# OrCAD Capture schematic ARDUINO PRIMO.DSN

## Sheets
1 00_Revision History: title: Revision History; rev: 3.0; company: dog hunter Inc.; note: Freedog; note: 8F-4, No.17, Ln. 91, Sec. 1,; note: Neihu Rd., Neihu Dist., Taipei City
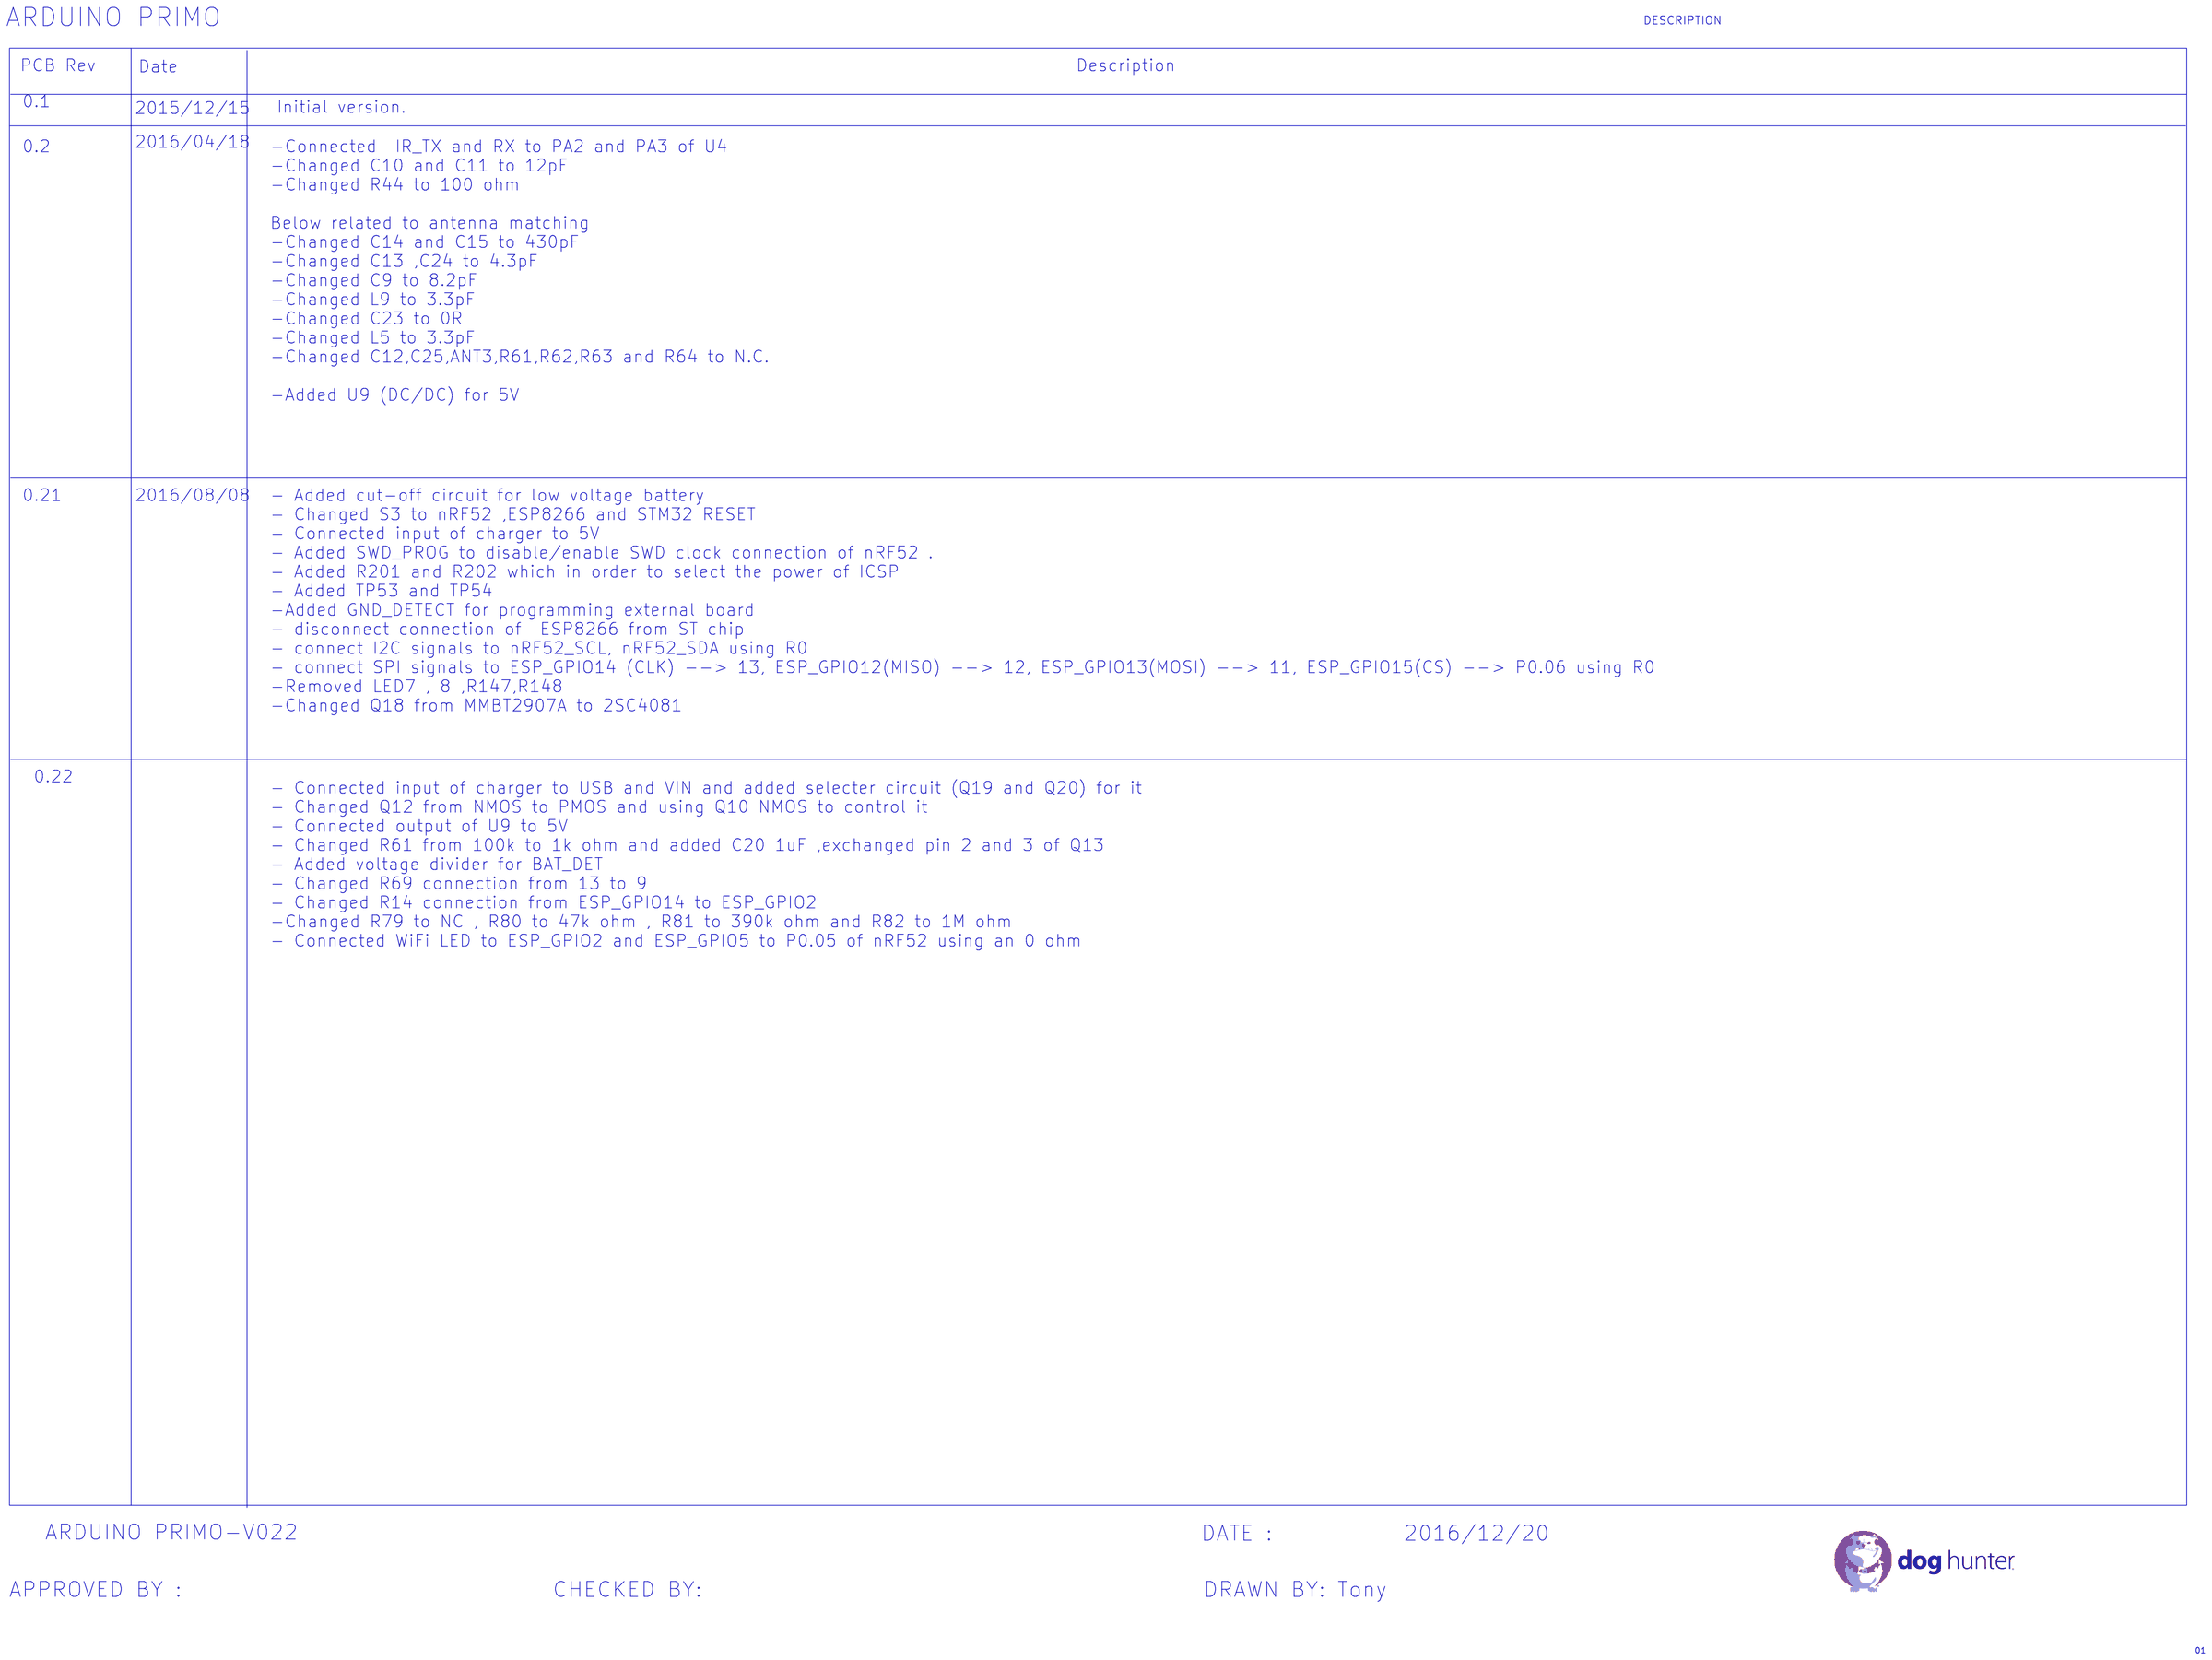
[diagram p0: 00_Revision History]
2 01_Block_Diagram: title: Block Diagram
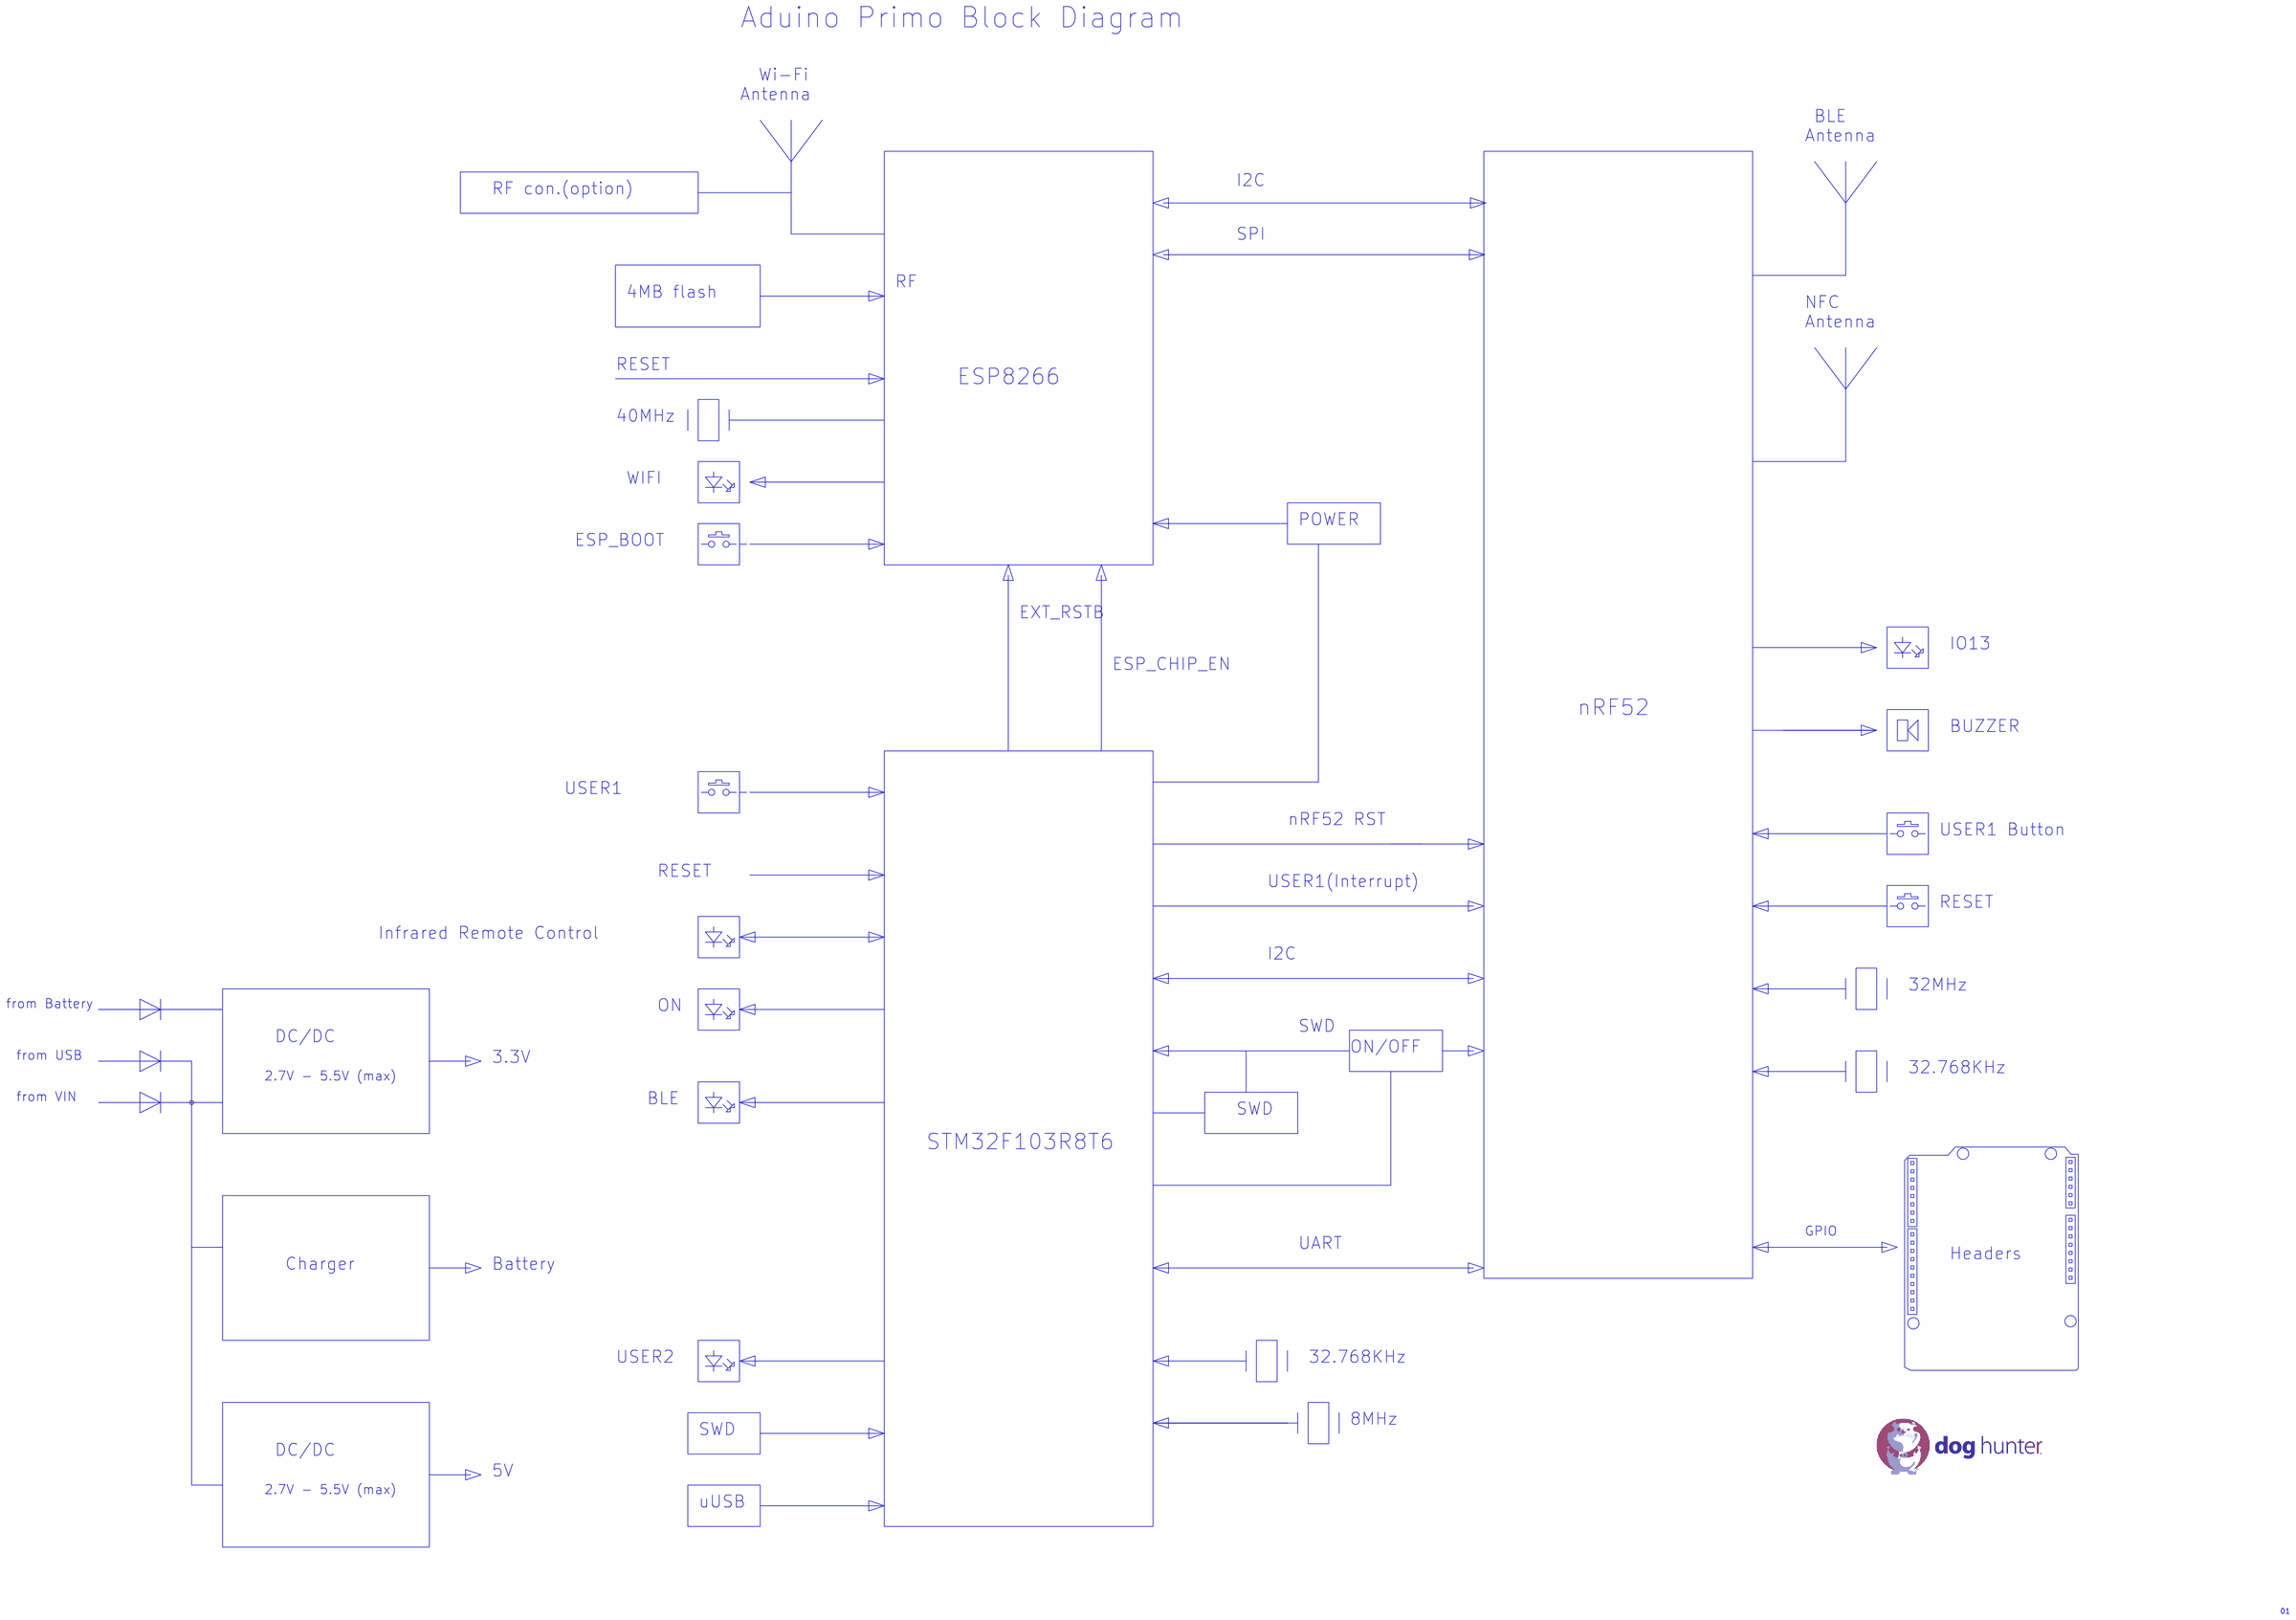
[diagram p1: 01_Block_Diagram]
3 02_Power_Block_Diagram: title: Power Block Diagram
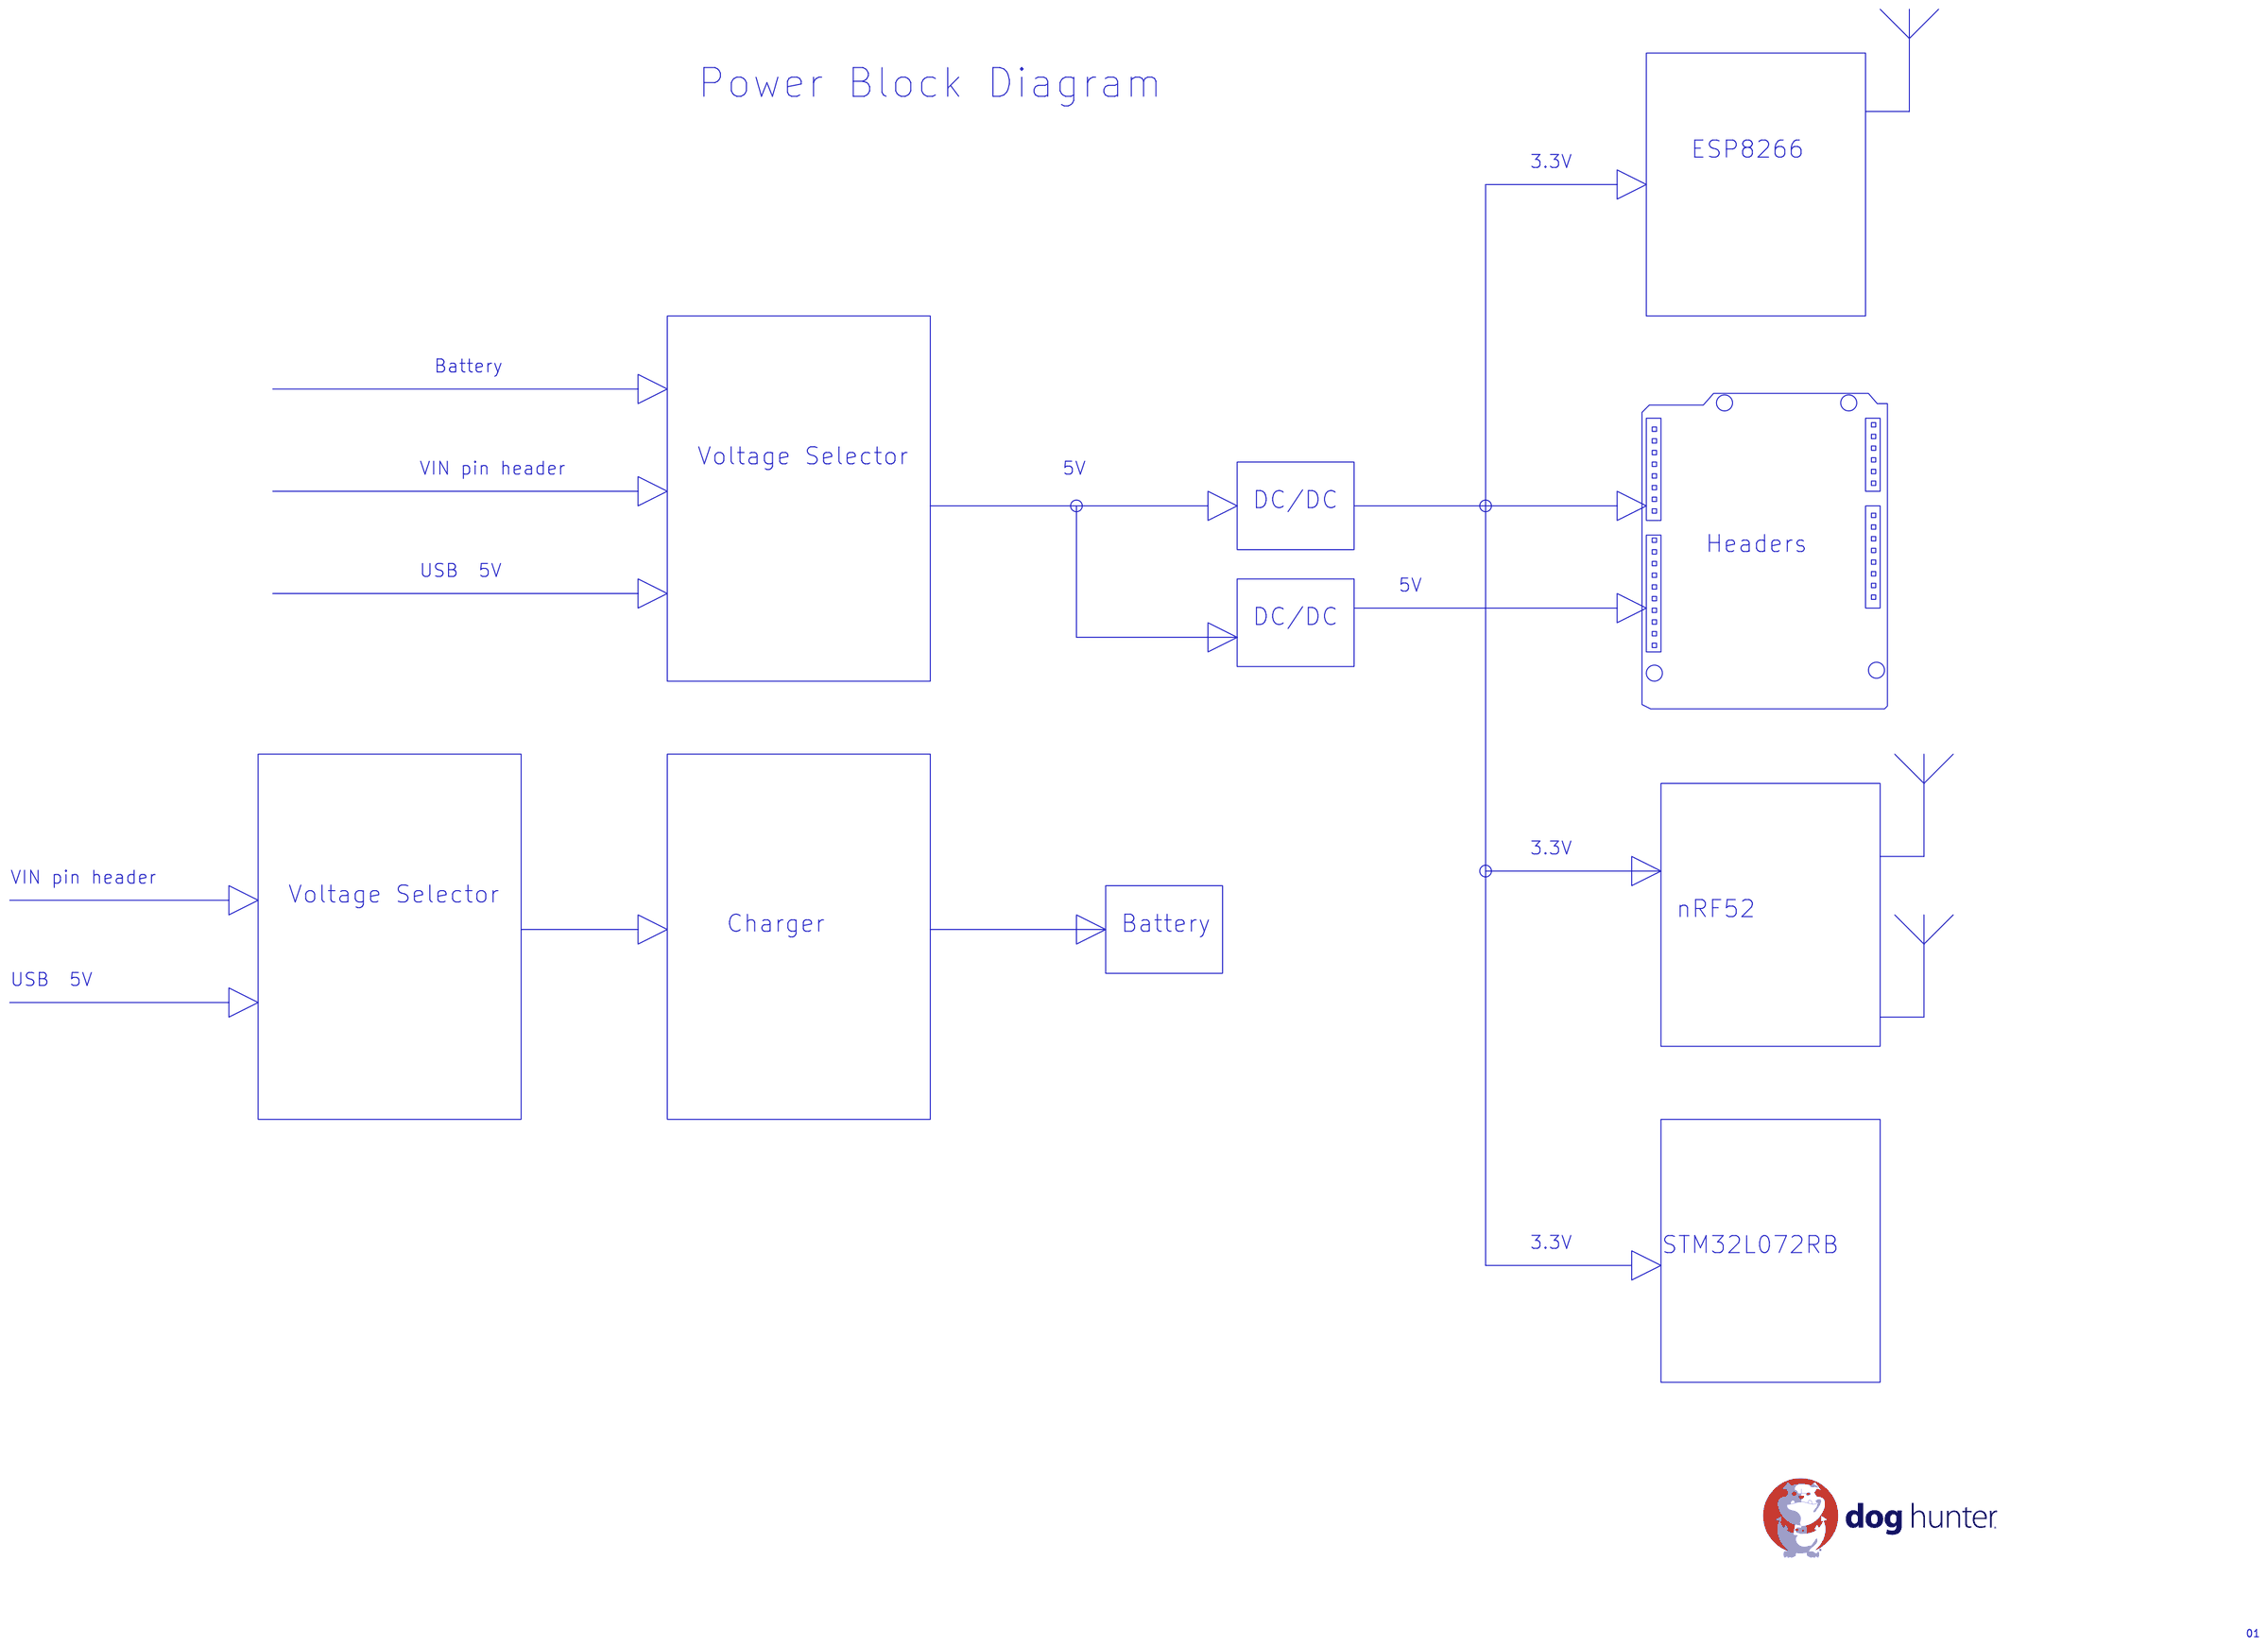
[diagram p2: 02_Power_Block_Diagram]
4 03_nRF52: size Custom; title: ATMEGA16U2 / ATMEGA328P
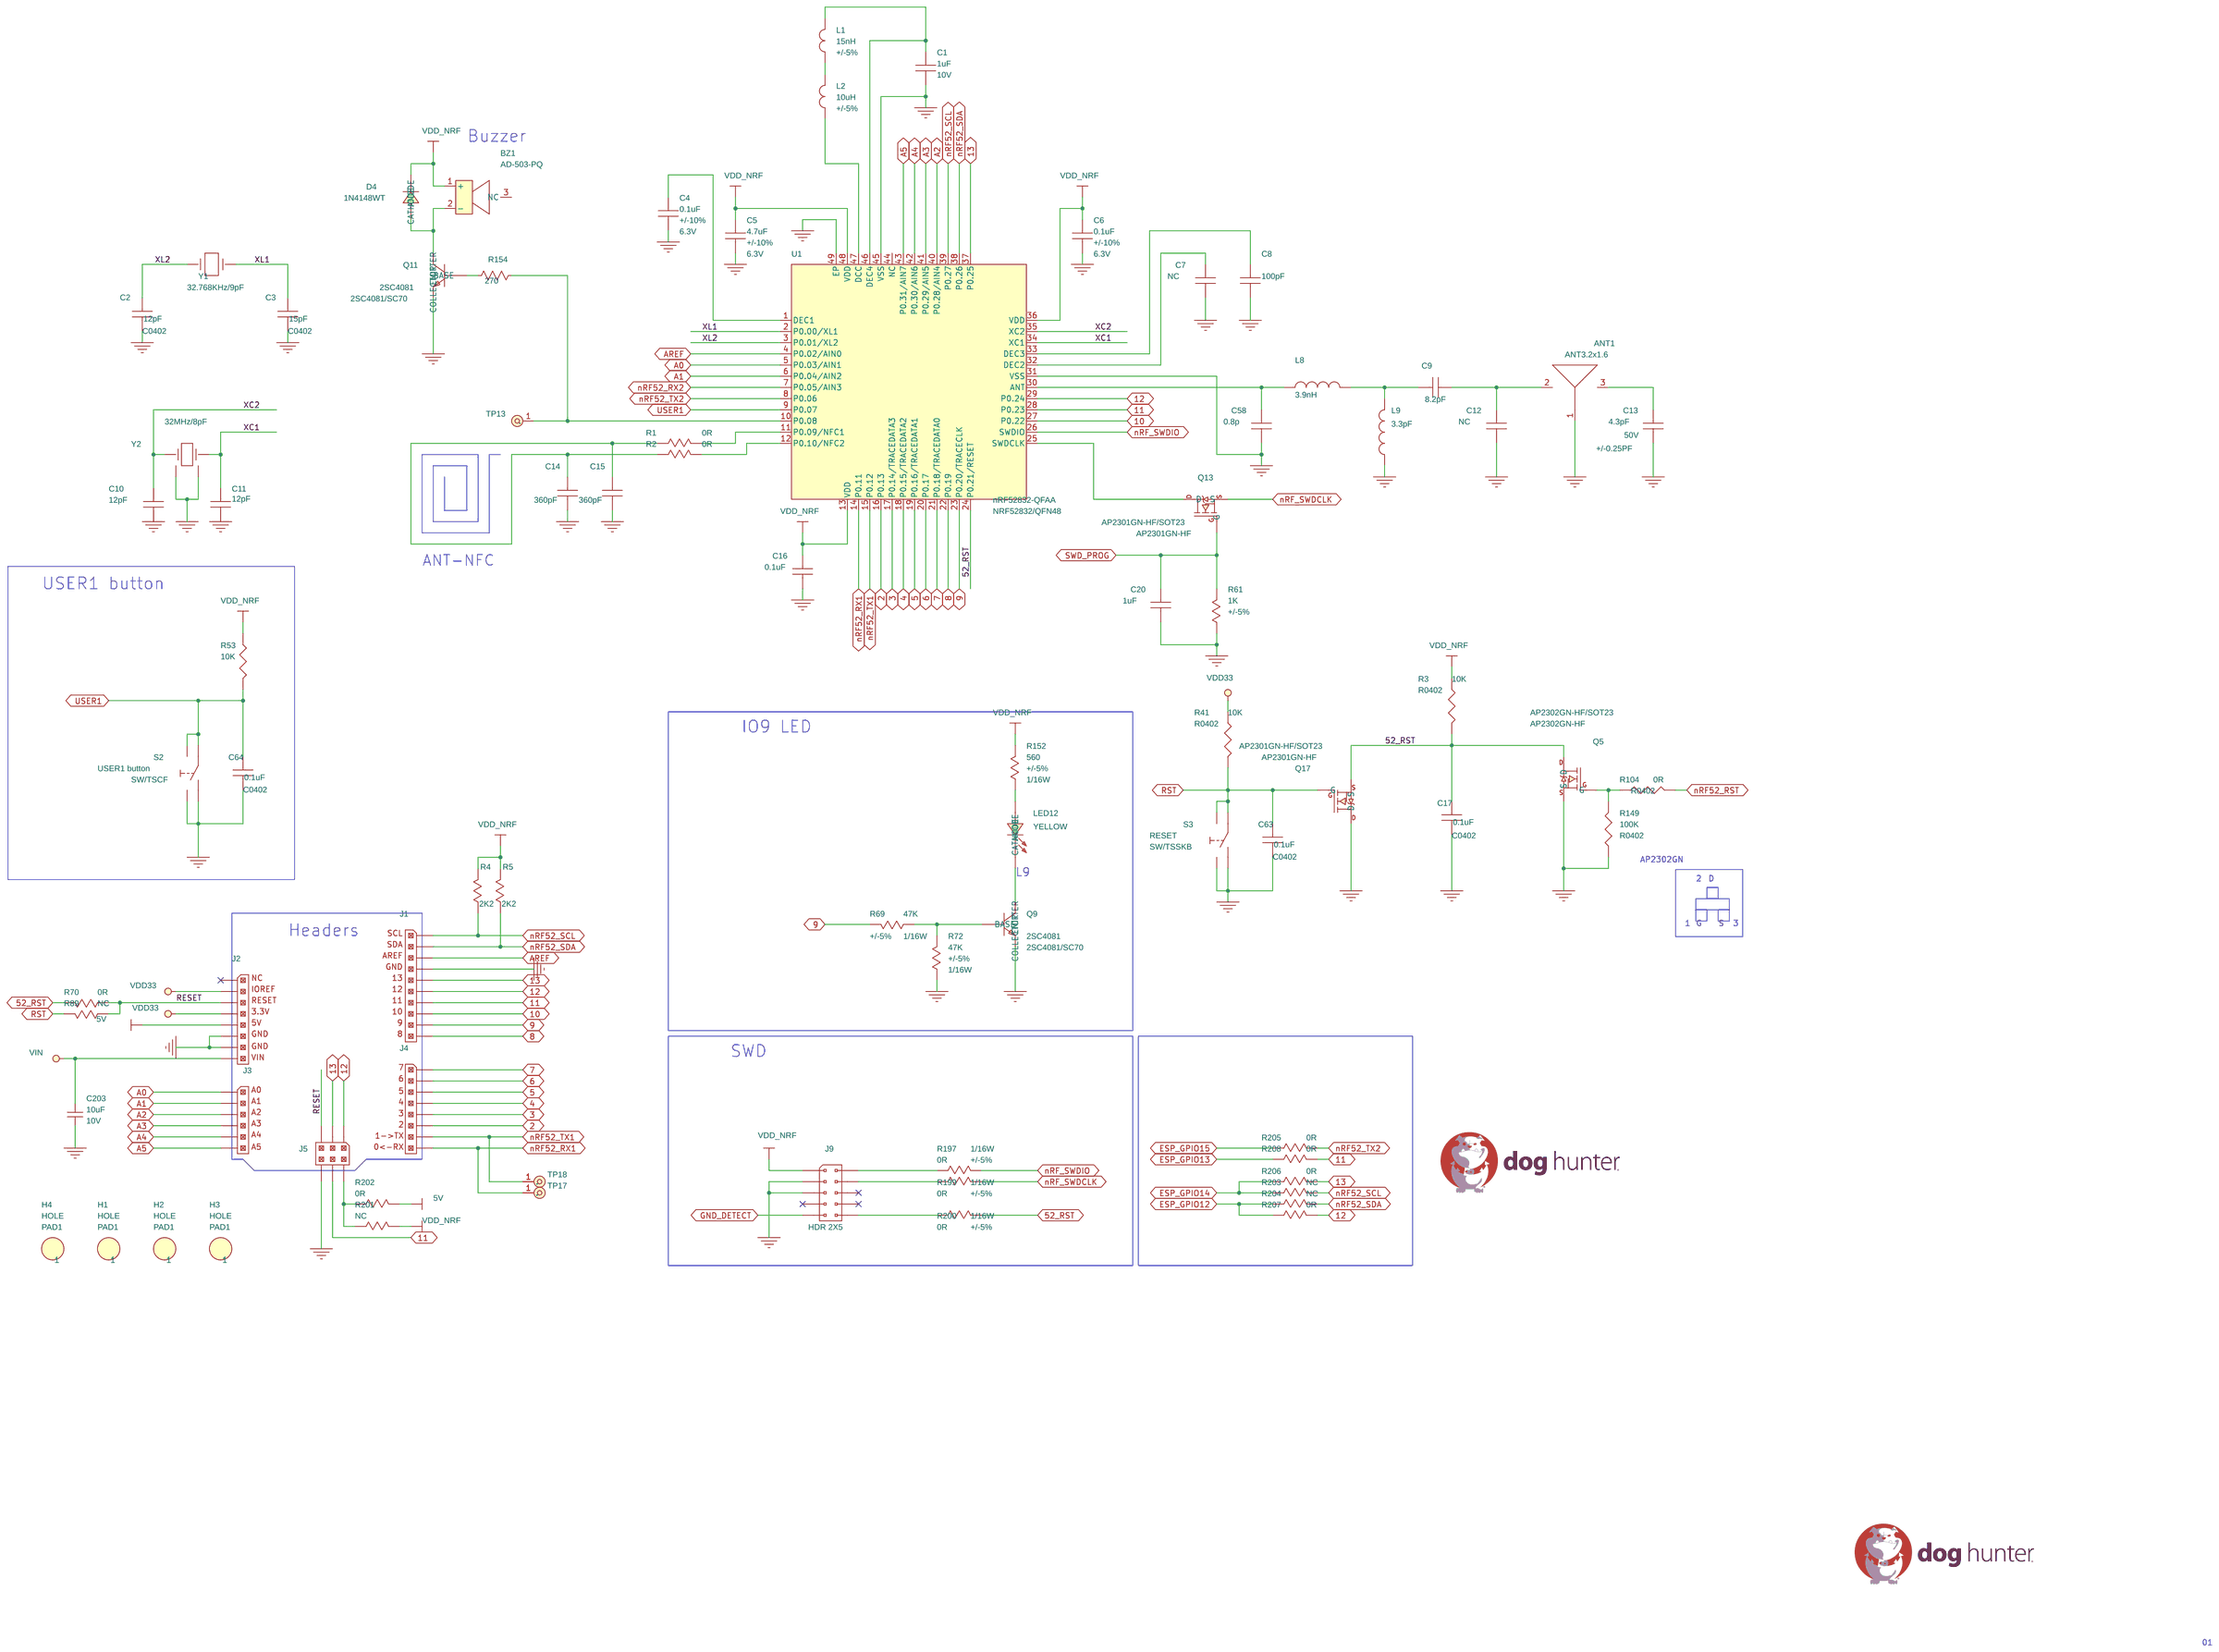
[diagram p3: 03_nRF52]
5 04_ESP8266: size A3; title: ESP8266
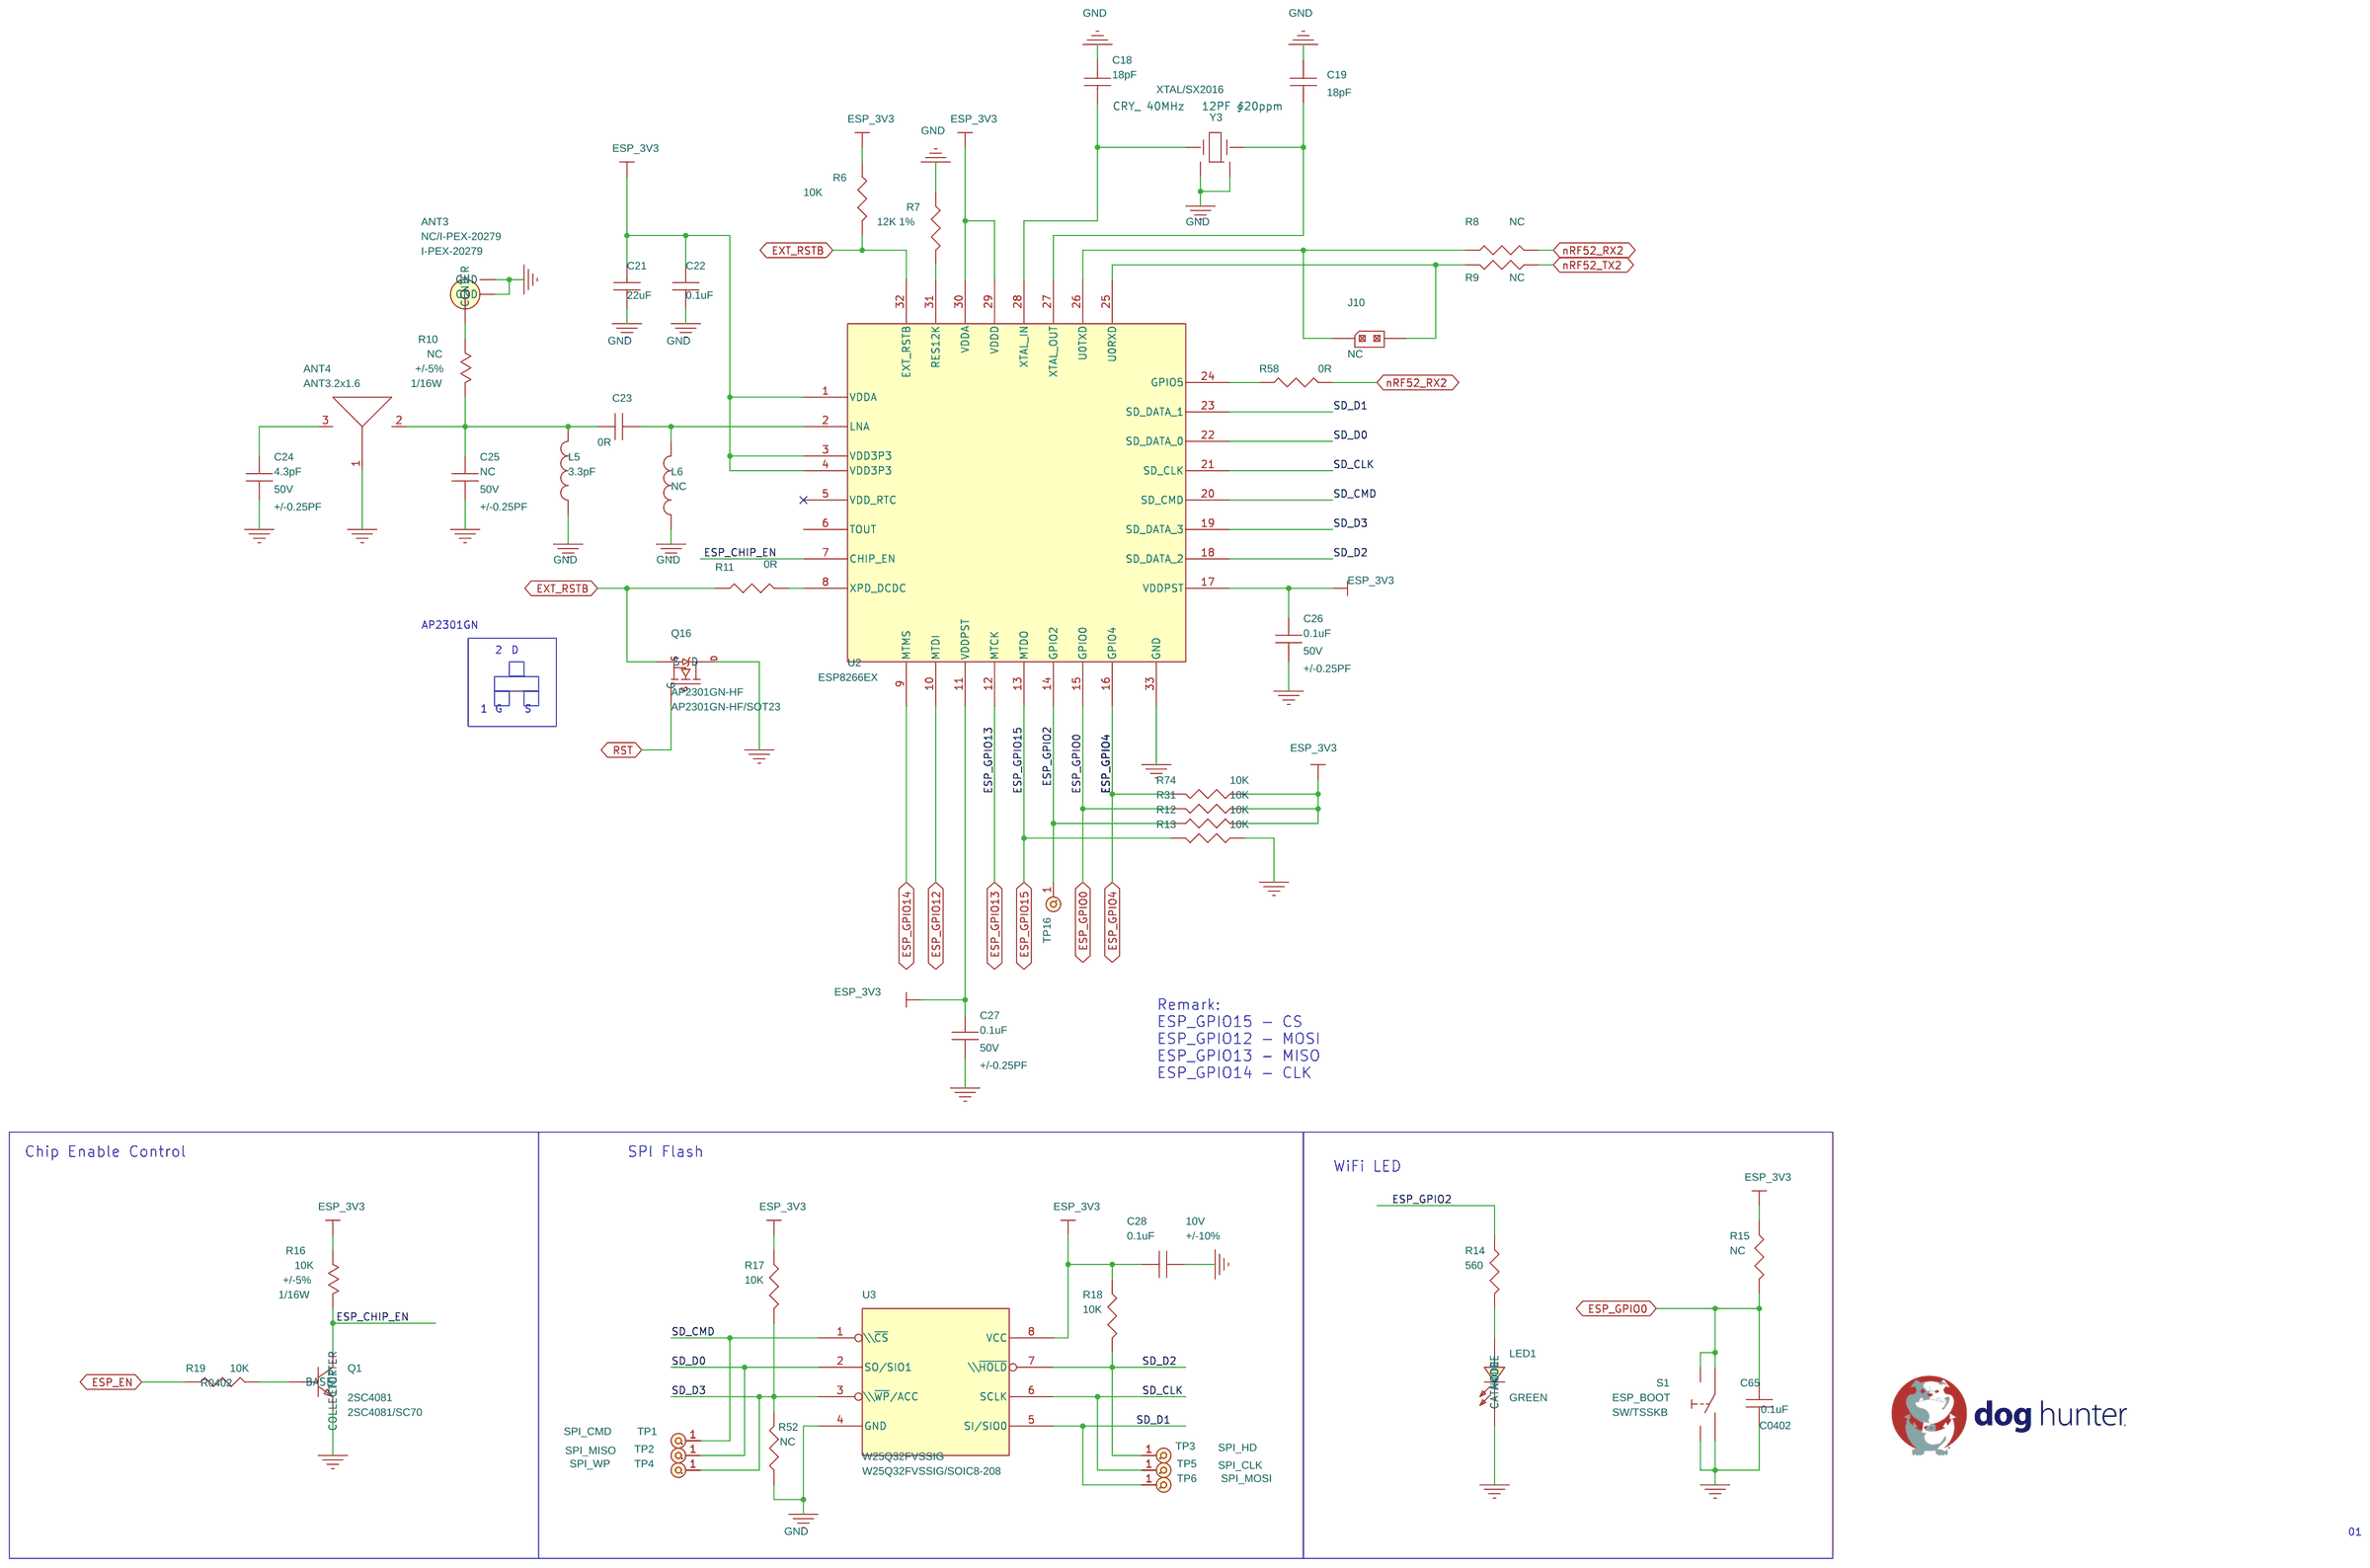
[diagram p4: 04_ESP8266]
6 05_ST: size A3; title: ST
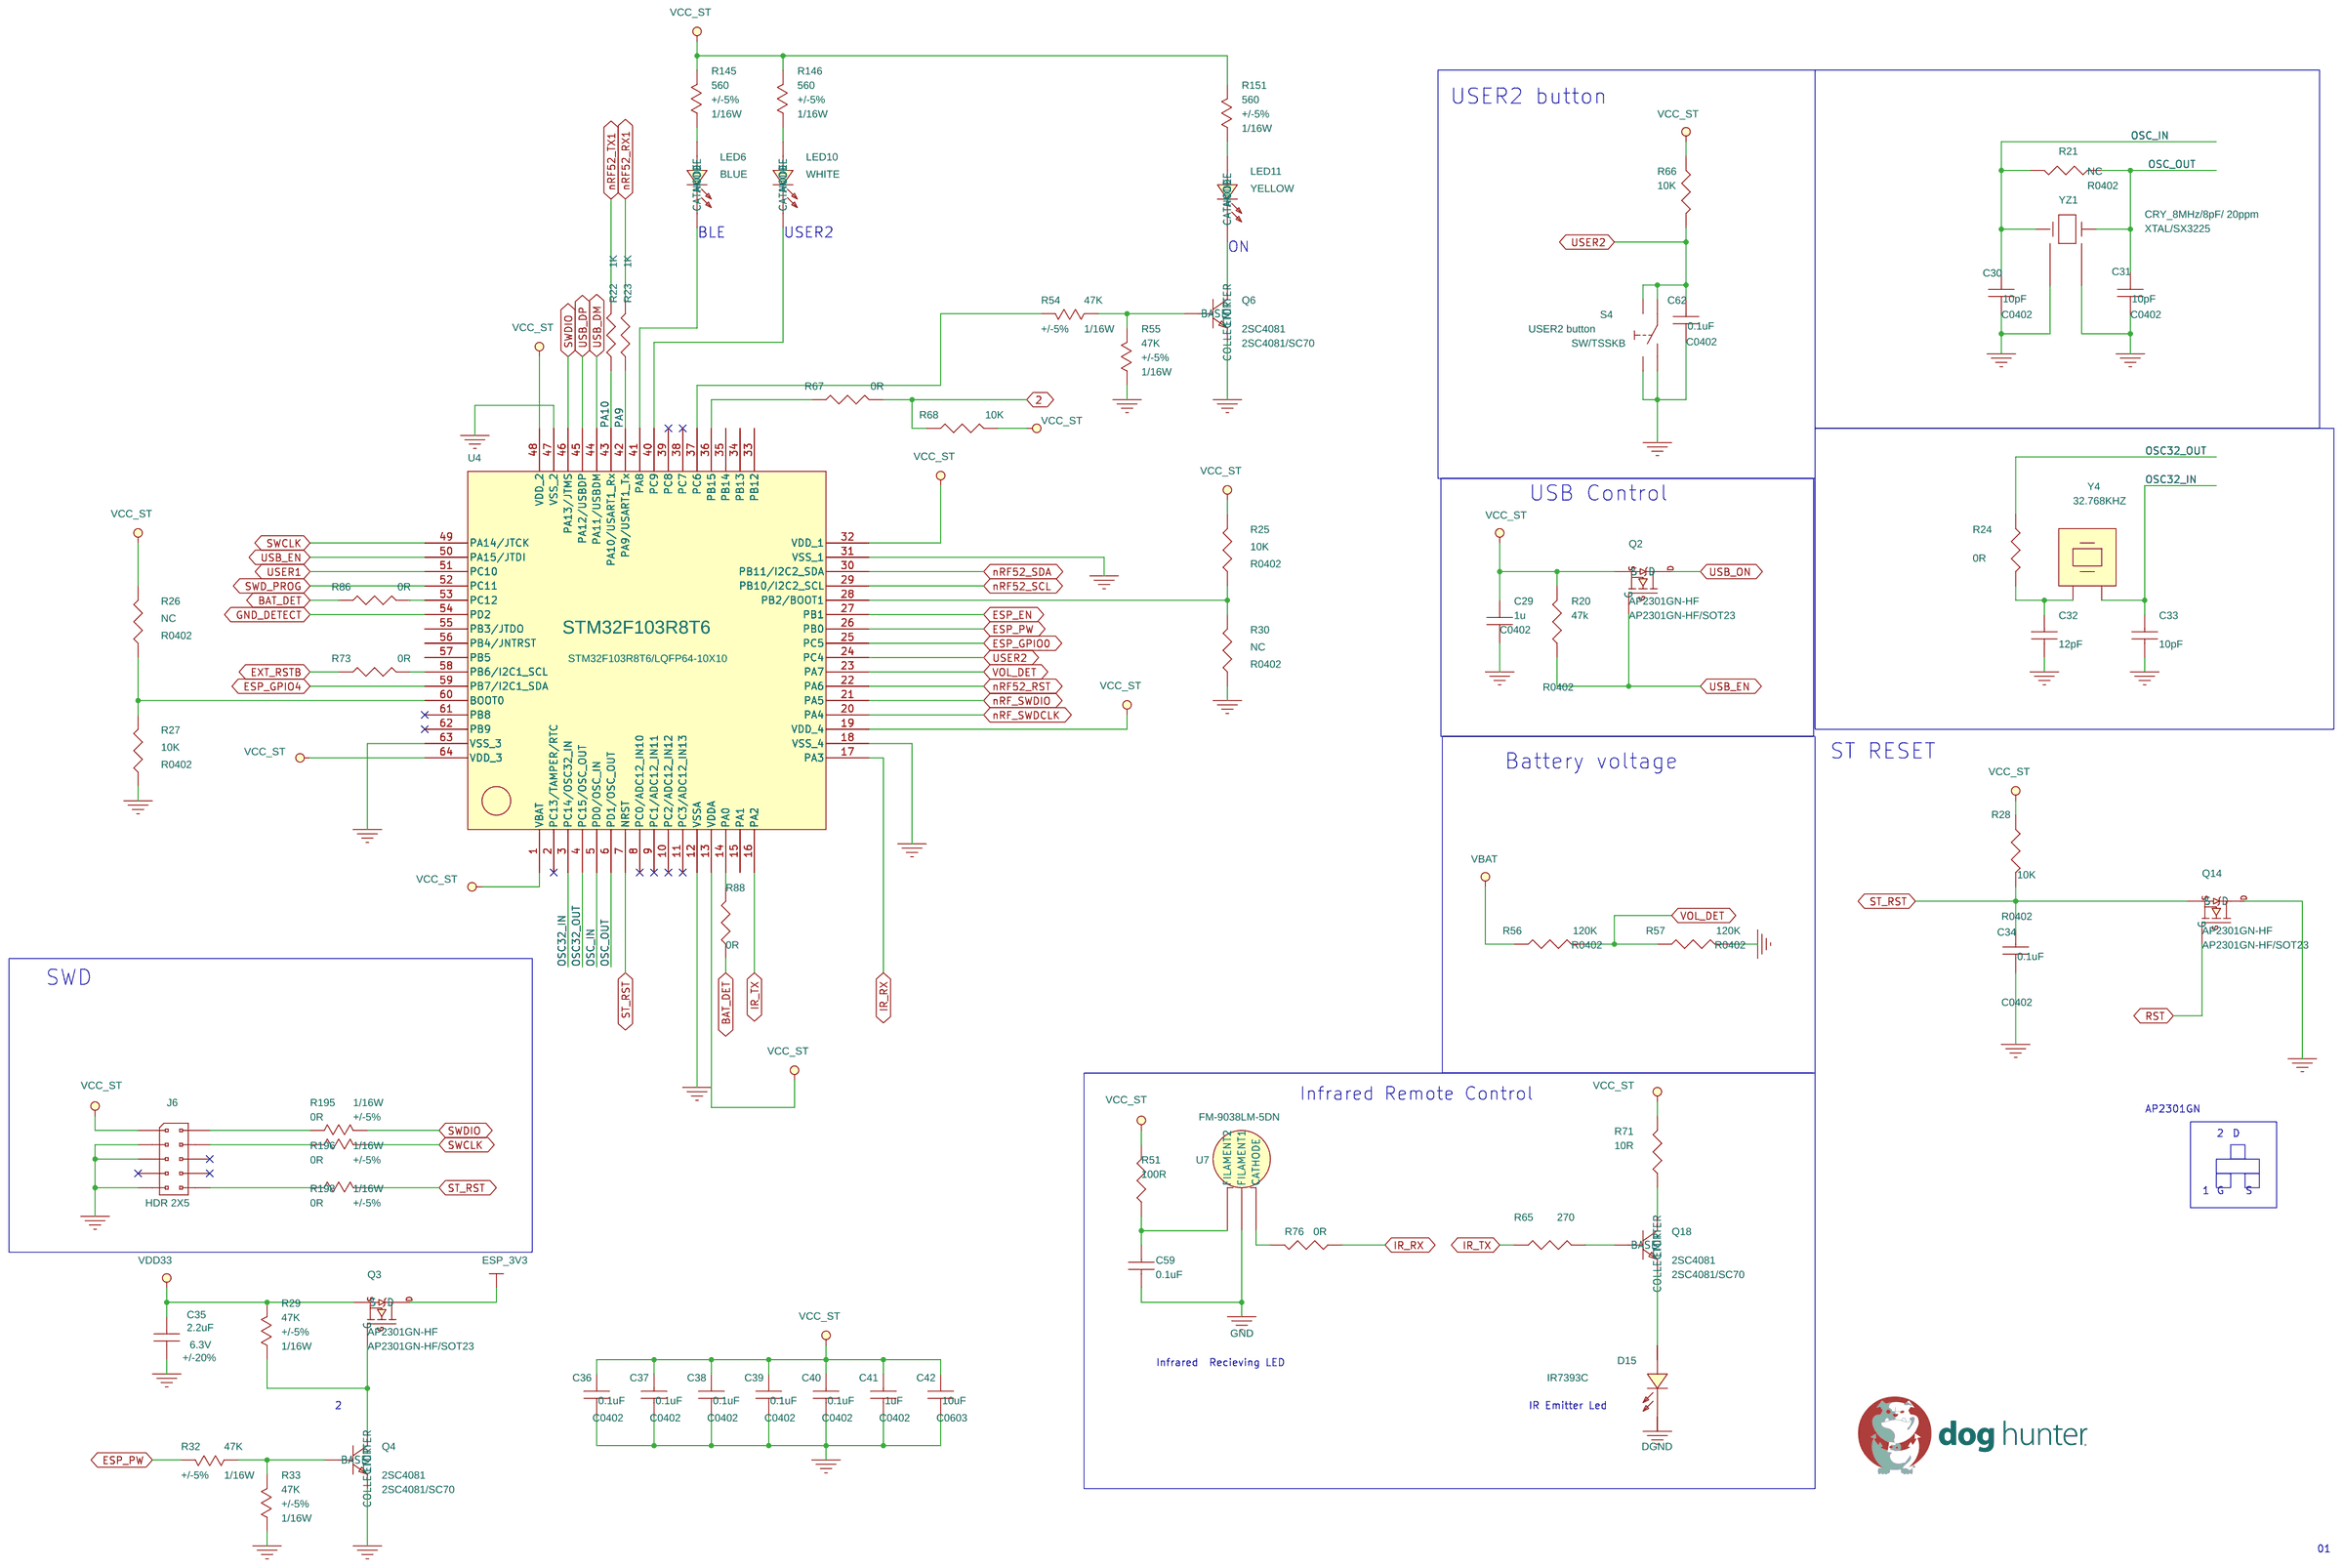
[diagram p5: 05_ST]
7 06_Power: size Custom; title: ST
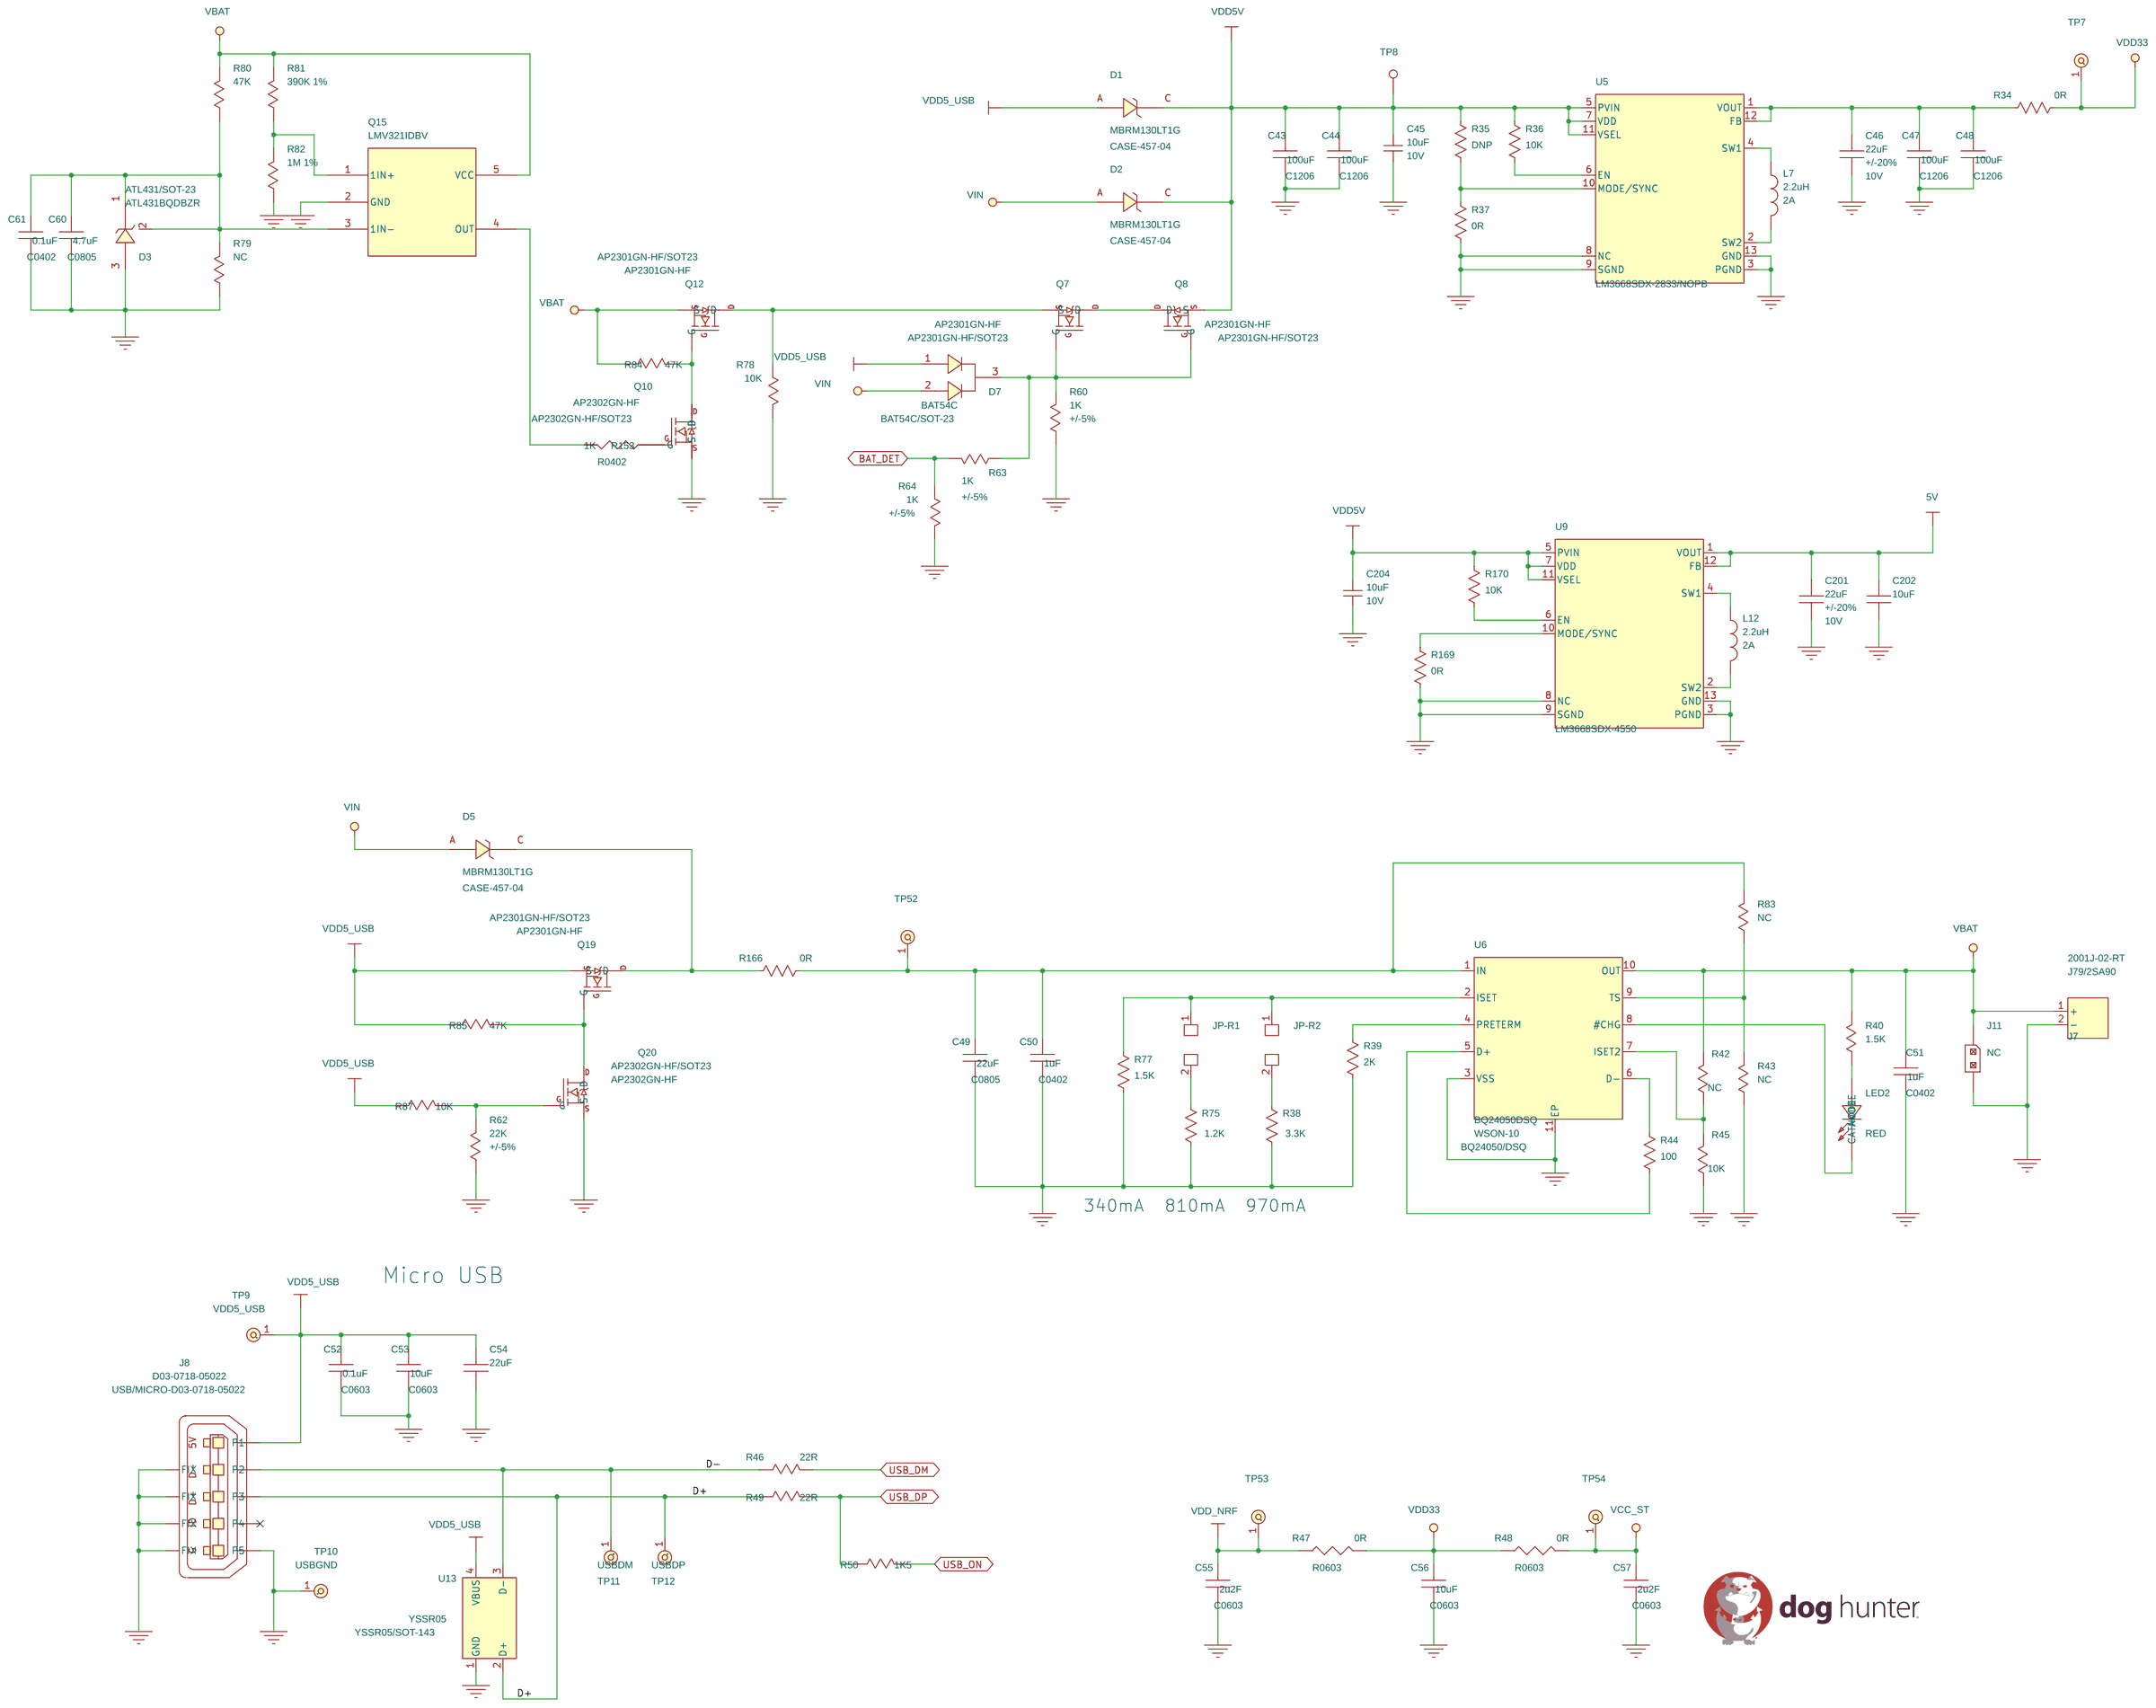
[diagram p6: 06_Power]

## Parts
sheet 03_nRF52
ANT1  ANT3.2x1.6  [ANT-3.2X1.6]
BZ1  AD-503-PQ  [AD-503-PQ]
C1  1uF  [C0402]
C2  12pF  [C0402]
C3  15pF  [C0402]
C4  0.1uF  [C0603]
C5  4.7uF  [C0603]
C6  0.1uF  [C0402]
C7  NC  [C0402]
C8  100pF  [C0402]
C9  8.2pF  [C0402]
C10  12pF  [C0402]
C11  12pF  [C0402]
C12  NC  [C0402]
C13  4.3pF  [C0402]
C14  360pF  [C0402]
C15  360pF  [C0402]
C16  0.1uF  [C0402]
C17  0.1uF  [C0402]
C20  1uF  [C0402]
C58  0.8p  [C0402]
C63  0.1uF  [C0402]
C64  0.1uF  [C0402]
C203  10uF  [C0805]
D4  1N4148WT  [SOD523]
H1  HOLE  [PAD1]
H2  HOLE  [PAD1]
H3  HOLE  [PAD1]
H4  HOLE  [PAD1]
J1  HEADER_2.54MM_VERT_PTH_10x1POS  [J100/10S]
J2  HEADER_2.54MM_VERT_PTH_8x1POS  [J100/8S]
J3  HEADER_2.54MM_VERT_PTH_6x1POS  [J100/6S]
J4  HEADER_2.54MM_VERT_PTH_8x1POS  [J100/8S]
J5  HEADER_2.54MM_VERT_PTH_3x2POS  [J100\6D]
J9  STRIP_1.27MM_VERT_PTH_5X2  [J50/10D]
L1  15nH  [L0402]
L2  10uH  [L0402]
L8  3.9nH  [L0402]
L9  3.3pF  [L0402]
LED12  YELLOW  [LED0603]
Q5  AP2302GN-HF  [AP2302GN-HF/SOT23]
Q9  2SC4081  [2SC4081/SC70]
Q11  2SC4081  [2SC4081/SC70]
Q13  AP2301GN-HF  [AP2301GN-HF/SOT23]
Q17  AP2301GN-HF  [AP2301GN-HF/SOT23]
R1  0R  [R0402]
R2  0R  [R0402]
R3  10K  [R0402]
R4  2K2  [R0402]
R5  2K2  [R0402]
R41  10K  [R0402]
R53  10K  [R0402]
R61  1K  [R0402]
R69  47K  [R0402]
R70  0R  [R0402]
R72  47K  [R0402]
R89  NC  [R0402]
R104  0R  [R0402]
R149  100K  [R0402]
R152  560  [R0402]
R154  270  [R0402]
R197  0R  [R0402]
R199  0R  [R0402]
R200  0R  [R0402]
R201  NC  [R0402]
R202  0R  [R0402]
R203  NC  [R0402]
R204  NC  [R0402]
R205  0R  [R0402]
R206  0R  [R0402]
R207  0R  [R0402]
R208  0R  [R0402]
S2  USER1 button  [SW/TSCF]
S3  RESET  [SW/TSSKB]
TP13  SPI_CMD  [PADA]
TP17  SPI_CMD  [PADA]
TP18  SPI_CMD  [PADA]
U1  nRF52832-QFAA  [NRF52832/QFN48]
Y1  32.768KHz/9pF  [XTAL/S2012R]
Y2  32MHz/8pF  [XTAL/SX2016]
sheet 04_ESP8266
ANT3  NC/I-PEX-20279  [I-PEX-20279]
ANT4  ANT3.2x1.6  [ANT-3.2X1.6]
C18  18pF  [C0402]
C19  18pF  [C0402]
C21  22uF  [C0603]
C22  0.1uF  [C0402]
C23  0R  [C0402]
C24  4.3pF  [C0402]
C25  NC  [C0402]
C26  0.1uF  [C0402]
C27  0.1uF  [C0402]
C28  0.1uF  [C0402]
C65  0.1uF  [C0402]
J10  NC  [J100/2S]
L5  3.3pF  [L0402]
L6  NC  [L0402]
LED1  GREEN  [LED0603]
Q1  2SC4081  [2SC4081/SC70]
Q16  AP2301GN-HF  [AP2301GN-HF/SOT23]
R6  10K  [R0402]
R7  12K 1%  [R0402]
R8  NC  [R0402]
R9  NC  [R0402]
R10  NC  [R0402]
R11  0R  [R0402]
R12  10K  [R0402]
R13  10K  [R0402]
R14  560  [R0402]
R15  NC  [R0402]
R16  10K  [R0402]
R17  10K  [R0402]
R18  10K  [R0402]
R19  10K  [R0402]
R31  10K  [R0402]
R52  NC  [R0402]
R58  0R  [R0402]
R74  10K  [R0402]
S1  ESP_BOOT  [SW/TSSKB]
TP1  SPI_CMD  [PADA]
TP2  SPI_MISO  [PADA]
TP3  SPI_HD  [PADA]
TP4  SPI_WP  [PADA]
TP5  SPI_CLK  [PADA]
TP6  SPI_MOSI  [PADA]
TP16  SPI_CMD  [PADA]
U2  ESP8266EX  [QFN32/ESP8266EX]
U3  W25Q32FVSSIG  [W25Q32FVSSIG/SOIC8-208]
Y3  CRY_ 40MHz   12PF ∮20ppm  [XTAL/SX2016]
sheet 05_ST
C29  1u  [C0402]
C30  10pF  [C0402]
C31  10pF  [C0402]
C32  12pF  [C0402]
C33  10pF  [C0402]
C34  0.1uF  [C0402]
C35  2.2uF  [C0402]
C36  0.1uF  [C0402]
C37  0.1uF  [C0402]
C38  0.1uF  [C0402]
C39  0.1uF  [C0402]
C40  0.1uF  [C0402]
C41  1uF  [C0402]
C42  10uF  [C0603]
C59  0.1uF  [C0603]
C62  0.1uF  [C0402]
D15  IR7393C  [IR7393C]
J6  STRIP_1.27MM_VERT_PTH_5X2  [J50/10D]
LED6  BLUE  [LED0603]
LED10  WHITE  [LED0603]
LED11  YELLOW  [LED0603]
Q2  AP2301GN-HF  [AP2301GN-HF/SOT23]
Q3  AP2301GN-HF  [AP2301GN-HF/SOT23]
Q4  2SC4081  [2SC4081/SC70]
Q6  2SC4081  [2SC4081/SC70]
Q14  AP2301GN-HF  [AP2301GN-HF/SOT23]
Q18  2SC4081  [2SC4081/SC70]
R20  47k  [R0402]
R21  NC  [R0402]
R22  1K  [R0402]
R23  1K  [R0402]
R24  0R  [R0402]
R25  10K  [R0402]
R26  NC  [R0402]
R27  10K  [R0402]
R28  10K  [R0402]
R29  47K  [R0402]
R30  NC  [R0402]
R32  47K  [R0402]
R33  47K  [R0402]
R51  100R  [R0402]
R54  47K  [R0402]
R55  47K  [R0402]
R56  120K  [R0402]
R57  120K  [R0402]
R65  270  [R0402]
R66  10K  [R0402]
R67  0R  [R0402]
R68  10K  [R0402]
R71  10R  [R0402]
R73  0R  [R0402]
R76  0R  [R0402]
R86  0R  [R0402]
R88  0R  [R0402]
R145  560  [R0402]
R146  560  [R0402]
R151  560  [R0402]
R195  0R  [R0402]
R196  0R  [R0402]
R198  0R  [R0402]
S4  USER2 button  [SW/TSSKB]
U4  STM32F103R8T6  [STM32F103R8T6/LQFP64-10X10]
U7  FM-9038LM-5DN  [IR/FM-9038LM-5DN]
Y4  32.768KHZ  [32768-CC7V-T1A]
YZ1  CRY_8MHz/8pF/ 20ppm  [XTAL/SX3225]
sheet 06_Power
C43  100uF  [C1206]
C44  100uF  [C1206]
C45  10uF  [C0805]
C46  22uF  [C0805]
C47  100uF  [C1206]
C48  100uF  [C1206]
C49  22uF  [C0805]
C50  1uF  [C0402]
C51  1uF  [C0402]
C52  0.1uF  [C0603]
C53  10uF  [C0603]
C54  22uF  [C0805]
C55  2u2F  [C0603]
C56  10uF  [C0603]
C57  2u2F  [C0603]
C60  4.7uF  [C0805]
C61  0.1uF  [C0402]
C201  22uF  [C0805]
C202  10uF  [C0603]
C204  10uF  [C0805]
D1  MBRM130LT1G  [CASE-457-04]
D2  MBRM130LT1G  [CASE-457-04]
D3  ATL431BQDBZR  [ATL431/SOT-23]
D5  MBRM130LT1G  [CASE-457-04]
D7  BAT54C  [BAT54C/SOT-23]
J7  2001J-02-RT  [J79/2SA90]
J8  MICRO_USB_5PIN_HORZ_SMD  [USB/MICRO-D03-0718-05022]
J11  NC  [J100/2S]
JP-R1  RESET-EN  [L0805-SHT]
JP-R2  RESET-EN  [L0805-SHT]
L7  2.2uH  [L/LPS4018]
L12  2.2uH  [L/LPS4018]
LED2  RED  [LED0603]
Q7  AP2301GN-HF  [AP2301GN-HF/SOT23]
Q8  AP2301GN-HF  [AP2301GN-HF/SOT23]
Q10  AP2302GN-HF  [AP2302GN-HF/SOT23]
Q12  AP2301GN-HF  [AP2301GN-HF/SOT23]
Q15  LMV321IDBV  [LMV321IDBV]
Q19  AP2301GN-HF  [AP2301GN-HF/SOT23]
Q20  AP2302GN-HF  [AP2302GN-HF/SOT23]
R34  0R  [R0402]
R35  DNP  [R0402]
R36  10K  [R0402]
R37  0R  [R0402]
R38  3.3K  [R0402]
R39  2K  [R0402]
R40  1.5K  [R0402]
R42  NC  [R0402]
R43  NC  [R0402]
R44  100  [R0402]
R45  10K  [R0402]
R46  22R  [R0402]
R47  0R  [R0603]
R48  0R  [R0603]
R49  22R  [R0402]
R50  1K5  [R0402]
R60  1K  [R0402]
R62  22K  [R0402]
R63  1K  [R0402]
R64  1K  [R0402]
R75  1.2K  [R0402]
R77  1.5K  [R0402]
R78  10K  [R0402]
R79  NC  [R0402]
R80  47K  [R0402]
R81  390K 1%  [R0402]
R82  1M 1%  [R0402]
R83  NC  [R0402]
R84  47K  [R0402]
R85  47K  [R0402]
R87  10K  [R0402]
R153  1K  [R0402]
R166  0R  [R0603]
R169  0R  [R0402]
R170  10K  [R0402]
TP7  VDD5V  [PADA]
TP8  TEST PAD  [PADA]
TP9  VDD5_USB  [PADA]
TP10  USBGND  [PADA]
TP11  USBDM  [PADA]
TP12  USBDP  [PADA]
TP52  VDD5V  [PADA]
TP53  VDD5V  [PADA]
TP54  VDD5V  [PADA]
U5  LM3668SDX-2833/NOPB  [LM3668-2833/WSON12]
U6  BQ24050DSQ  [BQ24050/DSQ]
U9  LM3668SDX-4550  [LM3668-2833/WSON12]
U13  YSSR05  [YSSR05/SOT-143]

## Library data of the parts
ANT1 ANT4 = ANT3.2x1.6
BZ1 = BUZZER_4P_0: BUZZER MAGN 3.6V 2.67KHZ SMT; Part Number: SMT-0927-S-6-R; Part Type: Buzzer
C1 = CAP: ATHEROS KEY: 031-104CK-022; AtherosDescription: CAP,0402,X7R,0.1uF,+/-10%,10V; CISPartType: Capacitor\0402; Tolerance: +/-10%; URL: 0; VendorDescription: equivalent of PHYCOMP / 04022F104M7B20D; VendorName: Yageo; VendorPart1: 662; Voltage: 10V
C2 C3 C30 C31 C43 C44 C47 C48 C52 C53 C62-C65 = 27PF_N_0402_5%
C4-C6 = CAP: ATHEROS KEY: 032-106CM-002; AtherosDescription: CAP,0603,X5R,10uF,+/-20%,10V; CISPartType: Capacitor\0603; Tolerance: +/-10%; Voltage: 6.3V
C7 C8 C12-C16 C20 C24-C27 C58 = CAP: ATHEROS KEY: 031-010CC-000; AtherosDescription: CAP,0402,NPO,1pF,+/-0.25pF,50V; CISPartType: Capacitor\0402; Tolerance: +/-0.25PF; Voltage: 50V
C9 C17-C19 C21-C23 C34 = CAP_NP
C10 C11 = CAP: ATHEROS KEY: 031-8R2CC-000; AtherosDescription: CAP,0402,NPO,8.2pF,+/-0.25pF,50V; CISPartType: Capacitor\0402; Tolerance: +/-0.25PF; Voltage: 50V
C45 C203 C204 = CAP_NP_v3: CAP CER 10UF 10V 10% X5R 0805; Package: 0805; Part Number: CAP_CER_10UF_10V_10%_X5R_ 0805; Part Type: Ceramic; Temp Coeff: X5R; Tolerance: 10%; Voltage: 10V
D4 = DIODE_TW: DIODE SWITCHING 75V 0.2A SOD523F; Current: 0.3A; Forward Voltage Drop: 1V a 50mA; Package: SOD-523F-2; Part Type: Rectifier; Voltage: 75V
H1-H4 = PAD
J1 = RECEPT_10X1_1: CONN RCPT 10POS .100" PTH; Part Type: Header
J2 = RECEPT_8X1_3: CONN RCPT 8POS .100" PTH; Part Type: Header
J3 = RECEPT_6X1_0: CONN RCPT 6POS .100" PTH; Part Type: Header
J4 = RECEPT_8X1_5: CONN RCPT 8POS .100" PTH; Part Type: Header
J5 = RECEPT_3X2: CONN RCPT 6POS DUAL .100" PTH; Part Type: Header
J6 J9 = STRIP_5X2: CONN HEADER 10POS DUAL .050" PTH; DESCR: HDR 2X5; Part Number: HEADER_1.27MM_VERT_PTH_5X2; Part Type: Berg Unshrouded
L1 = IND: ATHEROS KEY: 071-120LJ-000; AtherosDescription: IND,0402,12nH,+/-5%; CISPartType: Inductor\0402; Tolerance: +/-5%
L2 = IND_1: ATHEROS KEY: 071-120LJ-000; AtherosDescription: IND,0402,12nH,+/-5%; CISPartType: Inductor\0402; Tolerance: +/-5%
L5 L6 L8 L9 = INDUCTOR
LED6 LED10-LED12 = LED-0603-LTST-C190GKT_0: AtherosDescription: DIO,LED,GREEN CLEAR,0603,SMD; CISPartType: Diodes\LED
Q2 Q3 Q5 Q7 Q8 Q10 Q12-Q14 Q16 Q17 Q19 Q20 = MOSFET_N_0
Q1 Q4 Q6 Q9 Q18 = NPN_0: BJT NPN;50V;0.15A;SOT-323; Manufacturer: ROHM; yuhwei-footprint: SOT-323
Q11 = NPN_1: BJT NPN;50V;0.15A;SOT-323; Manufacturer: ROHM; yuhwei-footprint: SOT-323
R1 R2 R4 R5 = RES: ATHEROS KEY: 051-104RF-000; AtherosDescription: RES,0402,100K OHMS,+/-1%,1/16W; CISPartType: Resistor\0402; Tolerance: +/-1%; WATTAGE: 1/16W
R3 R47 R67 = R_1
R41 R73 = R_3
R6-R9 R11-R15 R31 R53 R58 R66 R74 R76 = RESISTOR_0
R10 R16 R29 R32 R33 R40 R42 R43 R45 R54 R55 R60-R64 R69 R70 R72 R78-R85 R87 R89 R145 R146 R151 R152 = RES: ATHEROS KEY: 051-103RJ-000; AtherosDescription: RES,0402,10K OHMS,+/-5%,1/16W; CISPartType: Resistor\0402; Tolerance: +/-5%; WATTAGE: 1/16W
R25 R104 R153 = R_2
R19 R23 R48 R149 = R
R154 = R_v3: RES 2.2K OHM 1/16W 5% 0402 SMD; Package: 0402; Part Number: RES_2.2K_OHM_1/16W_5%_0402_SMD; Part type: Thick film; Power: 1/16W; Tolerance: 5%
R195-R208 = RES: ATHEROS KEY: 051-102RJ-000; AtherosDescription: RES,0402,1K OHMS,+/-5%,1/16W; CISPartType: Resistor\0402; Tolerance: +/-5%; WATTAGE: 1/16W
S2 = SW_PUSHBUTTON_0
S1 S3 S4 = SW_PUSHBUTTON_2
TP1-TP7 TP9-TP13 TP16-TP18 TP52-TP54 = TP
U1 = nRF52832_0
Y1 = CRY_SM_24MHz_4P_0
Y2 = XTAL-TH-HC49-25MHz_3: AtherosDescription: XTAL,HC-49/S,Thru_Hole,25.000MHZ; CISPartType: Crystals
ANT3 = BNC_1
C28 = CAP: ATHEROS KEY: 031-104CK-022; AtherosDescription: CAP,0402,X7R,0.1uF,+/-10%,10V; CISPartType: Capacitor\0402; Tolerance: +/-10%; Voltage: 10V
J10 J11 = RECEPT_3X2_0: CONN RCPT 6POS DUAL .100" PTH; Part Number: HEADER_2.54MM_VERT_PTH_3x2POS; Part Type: Header
LED1 LED2 = LED-0603-LTST-C190GKT_0: AtherosDescription: DIO,LED,Yellow CLEAR,0603,SMD; CISPartType: Diodes\LED
R17 R18 R52 = R_0: P/N: 21-253-625101
U2 = ESP8080_5
U3 = MX25L3205D-8SOP: AtherosDescription: IC,Memory,MX25L6405DZNI-12G,64M-bit SPI FLASH, SO8; CISPartType: IC\Memory
Y3 = CRY_SM_24MHz_4P_1
C29 C32 C33 = CAP_NP_0
C35 = CAP: ATHEROS KEY: 030-104CK-001; AtherosDescription: CAP,0201,X5R,0.1UF,+/-10%,6.3V; CISPartType: Capacitor\0201; StandardCost-100K: 0; Tolerance: +/-20%; URL: 0; VendorDescription: CAP, MLCC, X5R, 0.1uF +/-10%, 10V, 0402, 7"T+R; VendorName: Yageo; VendorPartNumber: CC0402KRX5R6BB104; Voltage: 6.3V
C36-C42 C49-C51 C55-C57 C60 C61 = 0.1UF_0402_10V_10%
C59 = CAP
D15 = LED_1
R20 = R_8
R21 = RESISTOR_1: Type: 5%
R22 = R_10
R24 = R_0
R26 = RESISTOR_5: Type: 5%
R27 = RESISTOR_3: Type: 5%
R28 = R_9
R30 = RESISTOR_2: Type: 5%
R51 = RESISTOR_4
R56 = R_4
R57 = R_5
R65 = RESISTOR_6
R68 = R_6
R71 = RESISTOR
R86 = R_7
R88 = R_11
U4 = SM339Bx-80LQFP_14
U7 = TRIODE_1
Y4 = CRYSTAL_2
YZ1 = CRY_SM_24MHz_4P_6
C46 C201 = CAP: ATHEROS KEY: 033-226CM-001; AtherosDescription: CAP,0805,X5R,22uF,+/-20%,6.3V; CISPartType: Capacitor\0805; Tolerance: +/-20%; Voltage: 10V
C54 = CAP: ATHEROS KEY: 033-226CM-001; AtherosDescription: CAP,0805,X5R,22uF,+/-20%,6.3V; CISPartType: Capacitor\0805; Tolerance: +/-20%; Voltage: 6.3V
C202 = CAP: ATHEROS KEY: 032-106CM-001; AtherosDescription: CAP,0603,X5R,10uF,+/-20%,6.3V; CISPartType: Capacitor\0603; StandardCost-100K: 0; Tolerance: +/-20%; URL: 0; VendorDescription: CAP, MLCC, X5R, 1uF +/-10%, 10V, 0603, 7"T+R; VendorName: Yageo; VendorPart1: 309; VendorPartNumber: CC0603KRX5R6BB105; Voltage: 10V
D1 D2 D5 = BZX84C22_SOT_4: Foxlink_Description: DIODE,SCHOTTKY,SOD-123,0.5A 40V,MBR0540,FAIRCHILD,RoHS; Foxlink_PN: PN APPLY; PAGE: 17; Vendor: FAIRCHILD
D3 = BZX84C22_SOT_6: Foxlink_Description: DIODE,SCHOTTKY,SOD-123,0.5A 40V,MBR0540,FAIRCHILD,RoHS; Foxlink_PN: PN APPLY; PAGE: 17; Vendor: FAIRCHILD
D7 = BZX84C22_SOT_5: Foxlink_Description: DIODE,SCHOTTKY,SOD-123,0.5A 40V,MBR0540,FAIRCHILD,RoHS; Foxlink_PN: PN APPLY; PAGE: 17; Vendor: FAIRCHILD
J7 = CON3_0
J8 = USB_MINI_AB_RECEPTACLE_0: CONN MICRO USB; DESCR: D03-0718-05022; HEIGHT: 4.27MM; MFG_NAME01: TE Connectivity Ltd; MFG_PN01: 1734035-2; Part Type: USB/micro; ROHS: Yes
JP-R1 JP-R2 = CV201210_0
L7 L12 = INDUCTOR_v2: INDUCTOR 2.2uH ±20% 2A 4.0X4.0X1.8 SMD; Current: 2A; Package: 4.0 x 4.0 X 1.8(H); Part Number: IND_2.2UH_2A_SHIELDED_SMD; Part Type: Power Inductor; Resistance: 70 mOhm; Tolerance: ±20%
Q15 = RT8250_7: ATHEROS KEY: 170-00178-000; AtherosDescription: REG,RT8250,23V,3A,340 kHz STEP-DOWN CONV,SO; CISPartType: IC\Regulator
R34 = R_v3_7: RES 0.0 OHM 1/16W JUMP 0402 SMD; Package: 0402; Part Number: RES_0.0_OHM_1/16W_JUMP_0402_SMD; Part type: Thick film; Power: 1/16W; Tolerance: NA
R35 = R_v3_5: Do Not Place RES 0201; Package: 0201; Part Number: DNP_0201; Power: NA; Tolerance: NA
R36 = R_v3_6: RES 10K OHM 1/20W 5% 0201 SMD; Package: 0201; Part Number: RES_10K_OHM_1/20W_5%_0201_SMD; Part type: Thick film; Power: 1/20W; Tolerance: 5%
R37 = R_v3_2: RES 0.0 OHM 1/20W JUMP 0201 SMD; Package: 0201; Part Number: RES_0.0_OHM_1/20W_JUMP_0201_SMD; Part type: Thick film; Power: 1/20W; Tolerance: NA
R38 = R_v3_4: RES 0.0 OHM 1/20W JUMP 0201 SMD; Package: 0201; Part Number: RES_0.0_OHM_1/20W_JUMP_0201_SMD; Part type: Thick film; Power: 1/20W; Tolerance: NA
R39 = R_v3_8: RES 0.0 OHM 1/20W JUMP 0201 SMD; Package: 0201; Part Number: RES_0.0_OHM_1/20W_JUMP_0201_SMD; Part type: Thick film; Power: 1/20W; Tolerance: NA
R44 = R_v3: RES 0.0 OHM 1/20W JUMP 0201 SMD; Package: 0201; Part Number: RES_0.0_OHM_1/20W_JUMP_0201_SMD; Part type: Thick film; Power: 1/20W; Tolerance: NA
R46 R49 R50 = RES: ATHEROS KEY: 051-000RJ-000; AtherosDescription: RES,0402,0 OHMS,+/-5%,1/16W; CISPartType: Resistor\0402; Tolerance: +/-5%; WATTAGE: 1/16W
R75 = R_v3_9: RES 0.0 OHM 1/20W JUMP 0201 SMD; Package: 0201; Part Number: RES_0.0_OHM_1/20W_JUMP_0201_SMD; Part type: Thick film; Power: 1/20W; Tolerance: NA
R77 = R_v3_11: RES 0.0 OHM 1/20W JUMP 0201 SMD; Package: 0201; Part Number: RES_0.0_OHM_1/20W_JUMP_0201_SMD; Part type: Thick film; Power: 1/20W; Tolerance: NA
R166 = R_v3_10: RES 0.0 OHM 1/16W JUMP 0402 SMD; Package: 0402; Part Number: RES_0.0_OHM_1/16W_JUMP_0402_SMD; Part type: Thick film; Power: 1/16W; Tolerance: NA
R169 = R_v3_1: RES 0.0 OHM 1/20W JUMP 0201 SMD; Package: 0201; Part Number: RES_0.0_OHM_1/20W_JUMP_0201_SMD; Part type: Thick film; Power: 1/20W; Tolerance: NA
R170 = R_v3_3: RES 10K OHM 1/20W 5% 0201 SMD; Package: 0201; Part Number: RES_10K_OHM_1/20W_5%_0201_SMD; Part type: Thick film; Power: 1/20W; Tolerance: 5%
TP8 = TEST_PAD: Part Type: Testpoint
U5 = LM3668_1: IC REG BUCK BST SYNC ADJ 12-LLP; Package: WSON 12; Part Number: LM3668-2833; Part Type: Power/Switching
U6 = LT3652_1: IC BATTERY CHARGER 12-DFN; Manufacturer: LINEAR; Manufacturer Part Number: LT3652EMSE#PBF; Package: WSON-10; Part Number: LT3652EDD; Part Type: Power/Battery charger; RS: 761-8796P
U9 = LM3668_5: IC REG BUCK BST SYNC ADJ 12-LLP; Package: WSON 12; Part Number: LM3668-2833; Part Type: Power/Switching
U13 = RT9501_12

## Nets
5V: C201.Pin1 C202.1(Pin1) J2.5 R202.2(Pin2) U9.1(VOUT) U9.12(FB)
GND: ANT1.1 ANT3.2(GND) ANT3.3(GND) ANT4.1 C1.Pin2 C2.2 C3.2 C4.Pin2 C5.Pin2 C6.Pin2 C7.2(Pin2) C8.2(Pin2) C10.2(Pin2) C11.2(Pin2) C12.2(Pin2) C13.2(Pin2) C14.2(Pin2) C15.2(Pin2) C16.2(Pin2) C17.2 C18.2 C19.2 C20.2(Pin2) C21.2 C22.2 C24.2(Pin2) C25.2(Pin2) C26.2(Pin2) C27.2(Pin2) C28.2(Pin2) C29.2 C30.2 C31.2 C32.2 C33.2 C34.2 C35.Pin2 C36.2 C37.2 C38.2 C39.2 C40.2 C41.2 C42.2 C43.2 C44.2 C45.1 C46.Pin2 C47.2 C48.2 C49.2 C50.2 C51.2 C52.2 C53.2 C54.Pin2 C55.2 C56.2 C57.2 C58.2(Pin2) C59.2(Pin2) C60.2 C61.2 C62.2 C63.2 C64.2 C65.2 C201.Pin2 C202.2(Pin2) C203.1 C204.1 D3.3(ANODE) D15.2(CATHODE) J1.4 J2.6 J2.7 J5.6 J6.3 J6.5 J6.9 J7.2(-) J8.5(P5) J8.6(FIX) J8.7(FIX) J8.8(FIX) J8.9(FIX) J9.3 J9.5 J11.2 L5.1 L6.1 L9.2 LED1.2(CATHODE) Q1.1(EMITTER) Q4.1(EMITTER) Q5.3(S) Q6.1(EMITTER) Q9.1(EMITTER) Q10.3(S) Q11.1(EMITTER) Q14.2(D) Q15.2(GND) Q16.2(D) Q17.2(D) Q20.3(S) R7.1 R13.2 R27.1 R30.1 R33.1(Pin1) R37.1 R38.1 R39.1 R43.1(Pin1) R45.1(Pin1) R52.2 R55.1(Pin1) R57.2 R60.1(Pin1) R61.1(Pin1) R62.1(Pin1) R64.1(Pin1) R72.1(Pin1) R75.1 R77.1 R78.2(Pin2) R79.2(Pin2) R82.2(Pin2) R149.1 R169.1 S1.3 S1.4 S2.2 S2.4 S3.3 S3.4 S4.3 S4.4 TP10.1(.) U1.31(VSS) U1.45(VSS) U1.49(EP) U2.33(GND) U3.4(GND) U4.12(VSSA) U4.18(VSS_4) U4.31(VSS_1) U4.47(VSS_2) U4.63(VSS_3) U5.3(PGND) U5.8(NC) U5.9(SGND) U5.13(GND) U6.3(VSS) U6.11(EP) U7.2(FILAMENT1) U9.3(PGND) U9.8(NC) U9.9(SGND) U9.13(GND) U13.1(GND) Y2.2 Y2.4 Y3.2 Y3.4 YZ1.2 YZ1.4
GND_DETECT: J9.9 U4.54(PD2)
VBAT: C51.1 J7.1(+) J11.1 Q12.3(S) Q15.5(VCC) R40.2(Pin2) R42.2(Pin2) R56.1 R80.1(Pin1) R81.1(Pin1) R84.1(Pin1) U6.10(OUT)
VCC_ST: C29.1 C36.1 C37.1 C38.1 C39.1 C40.1 C41.1 C42.1 C57.1 J6.1 Q2.3(S) R20.2 R25.2 R26.2 R28.1 R48.2 R51.2 R66.1 R68.2 R71.2 R145.2(Pin2) R146.2(Pin2) R151.2(Pin2) TP54.1(.) U4.1(VBAT) U4.13(VDDA) U4.19(VDD_4) U4.32(VDD_1) U4.48(VDD_2) U4.64(VDD_3)
VDD5_USB: C52.1 C53.1 C54.Pin1 D1.A(ANODE) D7.1 J8.1(P1) Q19.3(S) R85.1(Pin1) R87.1(Pin1) TP9.1(.) U13.4(VBUS)
VDD5V: C43.1 C44.1 C45.2 C204.2 D1.C(CATHODE) D2.C(CATHODE) Q8.3(S) R35.2 R36.2 R170.2 TP8.1 U5.5(PVIN) U5.7(VDD) U5.11(VSEL) U9.5(PVIN) U9.7(VDD) U9.11(VSEL)
VDD33: C35.Pin1 C56.1 J2.2 J2.4 Q3.3(S) R29.2(Pin2) R34.2 R41.1 R47.2 R48.1 TP7.1(.)
VDD_nRF: BZ1.1(+) C5.Pin1 C6.Pin1 C16.1(Pin1) C55.1 D4.C(CATHODE) J9.1 R3.1 R4.2(Pin2) R5.2(Pin2) R47.1 R53.1 R152.2(Pin2) R201.2(Pin2) TP53.1(.) U1.13(VDD) U1.36(VDD) U1.48(VDD)
VIN: C203.2 D2.A(ANODE) D5.A(ANODE) D7.2 J2.8
2: J4.6 R67.2 R68.1 U1.16(P0.13)
3: J4.5 U1.17(P0.14/TRACEDATA3)
4: J4.4 U1.18(P0.15/TRACEDATA2)
5: J4.3 U1.19(P0.16/TRACEDATA1)
6: J4.2 U1.20(P0.17)
7: J4.1 U1.21(P0.18/TRACEDATA0)
8: J1.10 U1.22(P0.19)
9: J1.9 R69.2(Pin2) U1.23(P0.20/TRACECLK)
10: J1.8 U1.27(P0.22)
11: J1.7 J5.4 R208.2(Pin2) U1.28(P0.23)
12: J1.6 J5.1 R207.2(Pin2) U1.29(P0.24)
13: J1.5 J5.3 R206.2(Pin2) U1.37(P0.25)
52_RST: C17.1 Q5.2(D) Q17.3(S) R3.2 R70.2(Pin2) R200.2(Pin2) U1.24(P0.21/RESET)
A0: J3.1 U1.5(P0.03/AIN1)
A1: J3.2 U1.6(P0.04/AIN2)
A2: J3.3 U1.40(P0.28/AIN4)
A3: J3.4 U1.41(P0.29/AIN5)
A4: J3.5 U1.42(P0.30/AIN6)
A5: J3.6 U1.43(P0.31/AIN7)
AREF: J1.3 U1.4(P0.02/AIN0)
BAT_DET: R63.2(Pin2) R64.2(Pin2) R86.1 R88.1
D+: J8.3(P3) R49.1(Pin1) TP12.1(.) U13.2(D+)
D-: J8.2(P2) R46.1(Pin1) TP11.1(.) U13.3(D-)
ESP_3V3: C21.1 C22.1 C26.1(Pin1) C27.1(Pin1) C28.1(Pin1) Q3.2(D) R6.1 R12.2 R15.1 R16.2(Pin2) R17.1 R18.1 R31.2 R74.2 U2.1(VDDA) U2.3(VDD3P3) U2.4(VDD3P3) U2.11(VDDPST) U2.17(VDDPST) U2.29(VDDD) U2.30(VDDA) U3.8(VCC)
ESP_CHIP_EN: Q1.3(COLLECTOR) R16.1(Pin1) U2.7(CHIP_EN)
ESP_EN: R19.1 U4.27(PB1)
ESP_GPIO0: C65.1 R15.2 R31.1 S1.1 S1.2 U2.15(GPIO0) U4.25(PC5)
ESP_GPIO2: R12.1 R14.1 TP16.1(.) U2.14(GPIO2)
ESP_GPIO4: R74.1 U2.16(GPIO4) U4.59(PB7/I2C1_SDA)
ESP_GPIO12: R204.1(Pin1) R207.1(Pin1) U2.10(MTDI)
ESP_GPIO13: R208.1(Pin1) U2.12(MTCK)
ESP_GPIO14: R203.1(Pin1) R206.1(Pin1) U2.9(MTMS)
ESP_GPIO15: R13.1 R205.1(Pin1) U2.13(MTDO)
ESP_PW: R32.2(Pin2) U4.26(PB0)
EXT_RSTB: Q16.3(S) R6.2 R11.1 R73.1 U2.32(EXT_RSTB)
IR_RX: R76.1 U4.17(PA3)
IR_TX: R65.1 U4.16(PA2)
nRF52_RST: R104.2 U4.22(PA6)
nRF52_RX1: J4.8 R23.1 TP17.1(.) U1.14(P0.11)
nRF52_RX2: R8.2 R58.2 U1.7(P0.05/AIN3)
nRF52_SCL: J1.1 R4.1(Pin1) R203.2(Pin2) U1.39(P0.27) U4.29(PB10/I2C2_SCL)
nRF52_SDA: J1.2 R5.1(Pin1) R204.2(Pin2) U1.38(P0.26) U4.30(PB11/I2C2_SDA)
nRF52_TX1: J4.7 R22.1 TP18.1(.) U1.15(P0.12)
nRF52_TX2: R9.2 R205.2(Pin2) U1.8(P0.06)
nRF_SWDCLK: Q13.3(S) R199.2(Pin2) U4.20(PA4)
nRF_SWDIO: R197.2(Pin2) U1.26(SWDIO) U4.21(PA5)
OSC32_IN: C33.1 U4.3(PC14/OSC32_IN) Y4.2
OSC32_OUT: R24.1 U4.4(PC15/OSC_OUT)
OSC_IN: C30.1 R21.2 U4.5(PD0/OSC_IN) YZ1.1
OSC_OUT: C31.1 R21.1 U4.6(PD1/OSC_OUT) YZ1.3
PA9: R23.2 U4.42(PA9/USART1_Tx)
PA10: R22.2 U4.43(PA10/USART1_Rx)
RESET: J2.3 J5.5 R70.1(Pin1) R89.1(Pin1)
RST: C63.1 Q14.1(G) Q16.1(G) Q17.1(G) R41.2 R89.2(Pin2) S3.1 S3.2
SD_CLK: TP5.1(.) U2.21(SD_CLK) U3.6(SCLK)
SD_CMD: TP1.1(.) U2.20(SD_CMD) U3.1(\\~{CS})
SD_D0: TP2.1(.) U2.22(SD_DATA_0) U3.2(SO/SIO1)
SD_D1: TP6.1(.) U2.23(SD_DATA_1) U3.5(SI/SIO0)
SD_D2: R18.2 TP3.1(.) U2.18(SD_DATA_2) U3.7(\\~{HOLD})
SD_D3: R17.2 R52.1 TP4.1(.) U2.19(SD_DATA_3) U3.3(\\~{WP}/ACC)
ST_RST: C34.1 Q14.3(S) R28.2 R198.2(Pin2) U4.7(NRST)
SWCLK: R196.2(Pin2) U4.49(PA14/JTCK)
SWD_PROG: C20.1(Pin1) Q13.1(G) R61.2(Pin2) U4.52(PC11)
SWDIO: R195.2(Pin2) U4.46(PA13/JTMS)
USB_DM: R46.2(Pin2) U4.44(PA11/USBDM)
USB_DP: R49.2(Pin2) R50.1(Pin1) U4.45(PA12/USBDP)
USB_EN: Q2.1(G) R20.1 U4.50(PA15/JTDI)
USB_ON: Q2.2(D) R50.2(Pin2)
USER1: C64.1 R53.2 S2.1 S2.3 U1.9(P0.07) U4.51(PC10)
USER2: C62.1 R66.2 S4.1 S4.2 U4.24(PC4)
VOL_DET: R56.2 R57.1 U4.23(PA7)
XC1: C11.1(Pin1) U1.34(XC1) Y2.3
XC2: C10.1(Pin1) U1.35(XC2) Y2.1
XL1: C3.1 U1.2(P0.00/XL1) Y1.2
XL2: C2.1 U1.3(P0.01/XL2) Y1.1
N29622423: C19.1 U2.27(XTAL_OUT) Y3.3
N29622427: R7.2 U2.31(RES12K)
N29622443: C18.1 U2.28(XTAL_IN) Y3.1
N29622492: ANT4.2 C23.1 C25.1(Pin1) L5.2 R10.1(Pin1)
N29622523: C23.2 L6.2 U2.2(LNA)
N29681279: ANT3.1(CENTER) R10.2(Pin2)
N29682822: Q1.2(BASE) R19.2
N29703271: ANT4.3 C24.1(Pin1)
N29711557: C4.Pin1 U1.1(DEC1)
N29711617: C1.Pin1 L1.1 U1.46(DEC4)
N29711619: L1.2 L2.1
N29711621: L2.2 U1.47(DCC)
N29718561: C9.2 L8.1 L9.1
N29718563: ANT1.2 C9.1 C12.1(Pin1)
N29718671: ANT1.3 C13.1(Pin1)
N29719184: C7.1(Pin1) U1.32(DEC2)
N29719221: C8.1(Pin1) U1.33(DEC3)
N29719730: C14.1(Pin1) C15.1(Pin1) R1.1(Pin1) R2.1(Pin1)
N29720474: Q13.2(D) U1.25(SWDCLK)
N29722083: R1.2(Pin2) U1.11(P0.09/NFC1)
N29722092: R2.2(Pin2) U1.12(P0.10/NFC2)
N29736746: C32.1 R24.2 Y4.1
N29739750: R26.1 R27.2 U4.60(BOOT0)
N29742598: R36.1 U5.6(EN)
N29742636: R35.1 R37.2 U5.10(MODE/SYNC)
N29742659: C46.Pin1 C47.1 C48.1 R34.1 U5.1(VOUT) U5.12(FB)
N29742673: L7.1 U5.4(SW1)
N29742677: L7.2 U5.2(SW2)
N29749428: C49.1 C50.1 R83.2(Pin2) R166.2 TP52.1(.) U6.1(IN)
N29751041: JP-R1.1 JP-R2.1 R77.2 U6.2(ISET)
N29751343: R39.2 U6.4(PRETERM)
N29751472: LED2.1(ANODE) R40.1(Pin1)
N29752052: LED2.2(CATHODE) U6.8(#CHG)
N29752288: R43.2(Pin2) R83.1(Pin1) U6.9(TS)
N29752870: R42.1(Pin1) R45.2(Pin2) U6.7(ISET2)
N29753062: R44.1 U6.5(D+)
N29753210: R44.2 U6.6(D-)
N29759606: J10.1 R8.1 U2.26(U0TXD)
N29759627: J10.2 R9.1 U2.25(U0RXD)
N29760513: Q3.1(G) Q4.3(COLLECTOR) R29.1(Pin1)
N29760568: Q4.2(BASE) R32.1(Pin1) R33.2(Pin2)
N29761915: LED1.1(ANODE) R14.2
N29763263: R11.2 U2.8(XPD_DCDC)
N29767126: Q5.1(G) R104.1 R149.2
N29769565: LED6.1(ANODE) R145.1(Pin1)
N29770826: LED6.2(CATHODE) U4.41(PA8)
N29770835: LED10.2(CATHODE) U4.40(PC9)
N29771151: LED10.1(ANODE) R146.1(Pin1)
N29771203: LED11.1(ANODE) R151.1(Pin1)
N29774094: Q6.2(BASE) R54.1(Pin1) R55.2(Pin2)
N29774128: R54.2(Pin2) U4.37(PC6)
N29774130: LED11.2(CATHODE) Q6.3(COLLECTOR)
N29774811: J5.2 R201.1(Pin1) R202.1(Pin1)
N29782858: C58.1(Pin1) L8.2 U1.30(ANT)
N29783425: D7.3 Q7.1(G) Q8.1(G) R60.2(Pin2) R63.1(Pin1)
N29791234: J6.10 R198.1(Pin1)
N29791901: J6.2 R195.1(Pin1)
N29791908: J6.4 R196.1(Pin1)
N29792575: J9.10 R200.1(Pin1)
N29792671: J9.2 R197.1(Pin1)
N29792675: J9.4 R199.1(Pin1)
N29801747: R76.2 U7.1(CATHODE)
N29801753: C59.1(Pin1) R51.1 U7.3(FILAMENT2)
N29802891: Q18.2(BASE) R65.2
N29803013: Q18.3(COLLECTOR) R71.1
N29805095: R154.2 TP13.1(.) U1.10(P0.08)
N29814935: R67.1 U4.36(PB15)
N29821877: R25.1 R30.2 U4.28(PB2/BOOT1)
N29826203: LED12.1(ANODE) R152.1(Pin1)
N29826208: Q9.2(BASE) R69.1(Pin1) R72.2(Pin2)
N29826244: LED12.2(CATHODE) Q9.3(COLLECTOR)
N29829231: R73.2 U4.58(PB6/I2C1_SCL)
N29866286: Q7.2(D) Q8.2(D)
N29866566: Q7.3(S) Q12.2(D) R78.1(Pin1)
N29875020: JP-R1.2 R75.2
N29875023: JP-R2.2 R38.2
N29876395: C60.1 C61.1 D3.1(CATHODE) D3.2(REF) Q15.3(1IN-) R79.1(Pin1) R80.2(Pin2)
N29878843: Q15.1(1IN+) R81.2(Pin2) R82.1(Pin1)
N29890785: BZ1.2(-) D4.A(ANODE) Q11.3(COLLECTOR)
N29890834: Q11.2(BASE) R154.1
N29937575: D15.1(ANODE) Q18.1(EMITTER)
N29957462: Q15.4(OUT) R153.2
N29957645: R170.1 U9.6(EN)
N29957659: R169.2 U9.10(MODE/SYNC)
N29957681: L12.2 U9.2(SW2)
N29957685: L12.1 U9.4(SW1)
N29961730: Q10.2(D) Q12.1(G) R84.2(Pin2)
N29969694: D5.C(CATHODE) Q19.2(D) R166.1
N29976404: Q20.1(G) R62.2(Pin2) R87.2(Pin2)
N29976620: Q19.1(G) Q20.2(D) R85.2(Pin2)
N29997044: R86.2 U4.53(PC12)
N30002425: R58.1 U2.24(GPIO5)
N30002778: Q10.1(G) R153.1
N30011415: R88.2 U4.14(PA0)

Not connected (* = marked no-connect by the designer): BZ1 3(NC); H1 1; H2 1; H3 1; H4 1; J2 1*; J6 6* 7* 8*; J8 4(P4)*; J9 6* 7* 8*; U1 44(NC); U2 5(VDD_RTC)* 6(TOUT); U4 2(PC13/TAMPER/RTC)* 8(PC0/ADC12_IN10)* 9(PC1/ADC12_IN11)* 10(PC2/ADC12_IN12)* 11(PC3/ADC12_IN13)* 15(PA1) 33(PB12) 34(PB13) 35(PB14) 38(PC7)* 39(PC8)* 55(PB3/JTDO) 56(PB4/JNTRST) 57(PB5) 61(PB8)* 62(PB9)*

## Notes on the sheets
sheet 1
- ARDUINO PRIMO
- DESCRIPTION
- PCB Rev
- Date
- Description
- 0.1
- 2015/12/15
- Initial version.
- 0.2
- 2016/04/18
- -Connected  IR_TX and RX to PA2 and PA3 of U4
  -Changed C10 and C11 to 12pF
  -Changed R44 to 100 ohm
  Below related to antenna matching
  -Changed C14 and C15 to 430pF
  -Changed C13 ,C24 to 4.3pF
  -Changed C9 to 8.2pF
  -Changed L9 to 3.3pF
  -Changed C23 to 0R
  -Changed L5 to 3.3pF
  -Changed C12,C25,ANT3,R61,R62,R63 and R64 to N.C.
  -Added U9 (DC/DC) for 5V
- 0.21
- 2016/08/08
- - Added cut-off circuit for low voltage battery
  - Changed S3 to nRF52 ,ESP8266 and STM32 RESET
  - Connected input of charger to 5V
  - Added SWD_PROG to disable/enable SWD clock connection of nRF52 .
  - Added R201 and R202 which in order to select the power of ICSP
  - Added TP53 and TP54
  -Added GND_DETECT for programming external board
  - disconnect connection of  ESP8266 from ST chip
  - connect I2C signals to nRF52_SCL, nRF52_SDA using R0
  - connect SPI signals to ESP_GPIO14 (CLK) --> 13, ESP_GPIO12(MISO) --> 12, ESP_GPIO13(MOSI) --> 11, ESP_GPIO15(CS) --> P0.06 using R0
  -Removed LED7 , 8 ,R147,R148
  -Changed Q18 from MMBT2907A to 2SC4081
- 0.22
- - Connected input of charger to USB and VIN and added selecter circuit (Q19 and Q20) for it
  - Changed Q12 from NMOS to PMOS and using Q10 NMOS to control it
  - Connected output of U9 to 5V
  - Changed R61 from 100k to 1k ohm and added C20 1uF ,exchanged pin 2 and 3 of Q13
  - Added voltage divider for BAT_DET
  - Changed R69 connection from 13 to 9
  - Changed R14 connection from ESP_GPIO14 to ESP_GPIO2
  -Changed R79 to NC , R80 to 47k ohm , R81 to 390k ohm and R82 to 1M ohm
  - Connected WiFi LED to ESP_GPIO2 and ESP_GPIO5 to P0.05 of nRF52 using an 0 ohm
- ARDUINO PRIMO-V022
- DATE :
- 2016/12/20
- APPROVED BY :
- CHECKED BY:
- DRAWN BY: Tony
- 01
sheet 2
- Aduino Primo Block Diagram
- Wi-Fi
  Antenna
- BLE
  Antenna
- RF con.(option)
- I2C
- SPI
- RF
- 4MB flash
- NFC
  Antenna
- RESET
- ESP8266
- 40MHz
- WIFI
- POWER
- ESP_BOOT
- EXT_RSTB
- IO13
- ESP_CHIP_EN
- nRF52
- BUZZER
- USER1
- nRF52 RST
- USER1 Button
- RESET
- USER1(Interrupt)
- RESET
- Infrared Remote Control
- I2C
- 32MHz
- from Battery
- ON
- SWD
- DC/DC
- ON/OFF
- from USB
- 3.3V
- 32.768KHz
- 2.7V - 5.5V (max)
- from VIN
- BLE
- SWD
- STM32F103R8T6
- GPIO
- UART
- Headers
- Charger
- Battery
- USER2
- 32.768KHz
- 8MHz
- SWD
- DC/DC
- 5V
- 2.7V - 5.5V (max)
- uUSB
- 01
sheet 3
- Power Block Diagram
- ESP8266
- 3.3V
- Battery
- Voltage Selector
- VIN pin header
- 5V
- DC/DC
- Headers
- USB  5V
- 5V
- DC/DC
- 3.3V
- VIN pin header
- Voltage Selector
- nRF52
- Charger
- Battery
- USB  5V
- 3.3V
- STM32L072RB
- 01
sheet 4
- Buzzer
- ANT-NFC
- USER1 button
- IO9 LED
- AP2302GN
- L9
- 2
- D
- 1
- G
- S
- 3
- Headers
- SWD
- 01
sheet 5
- AP2301GN
- 2
- D
- 1
- G
- S
- Remark:
  ESP_GPIO15 - CS
  ESP_GPIO12 - MOSI
  ESP_GPIO13 - MISO
  ESP_GPIO14 - CLK
- Chip Enable Control
- SPI Flash
- WiFi LED
- 01
sheet 6
- USER2 button
- BLE
- USER2
- ON
- USB Control
- ST RESET
- Battery voltage
- SWD
- Infrared Remote Control
- AP2301GN
- 2
- D
- 1
- G
- S
- Infrared  Recieving LED
- 2
- IR Emitter Led
- 01
sheet 7
- 340mA
- 810mA
- 970mA
- Micro USB
